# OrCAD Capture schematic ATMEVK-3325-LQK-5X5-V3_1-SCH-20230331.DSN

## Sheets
1 10. VCCIO Source: size B; title: ATM3325 EVALUATION BOARD; rev: 3.1; note: 082-30-610-xxxx
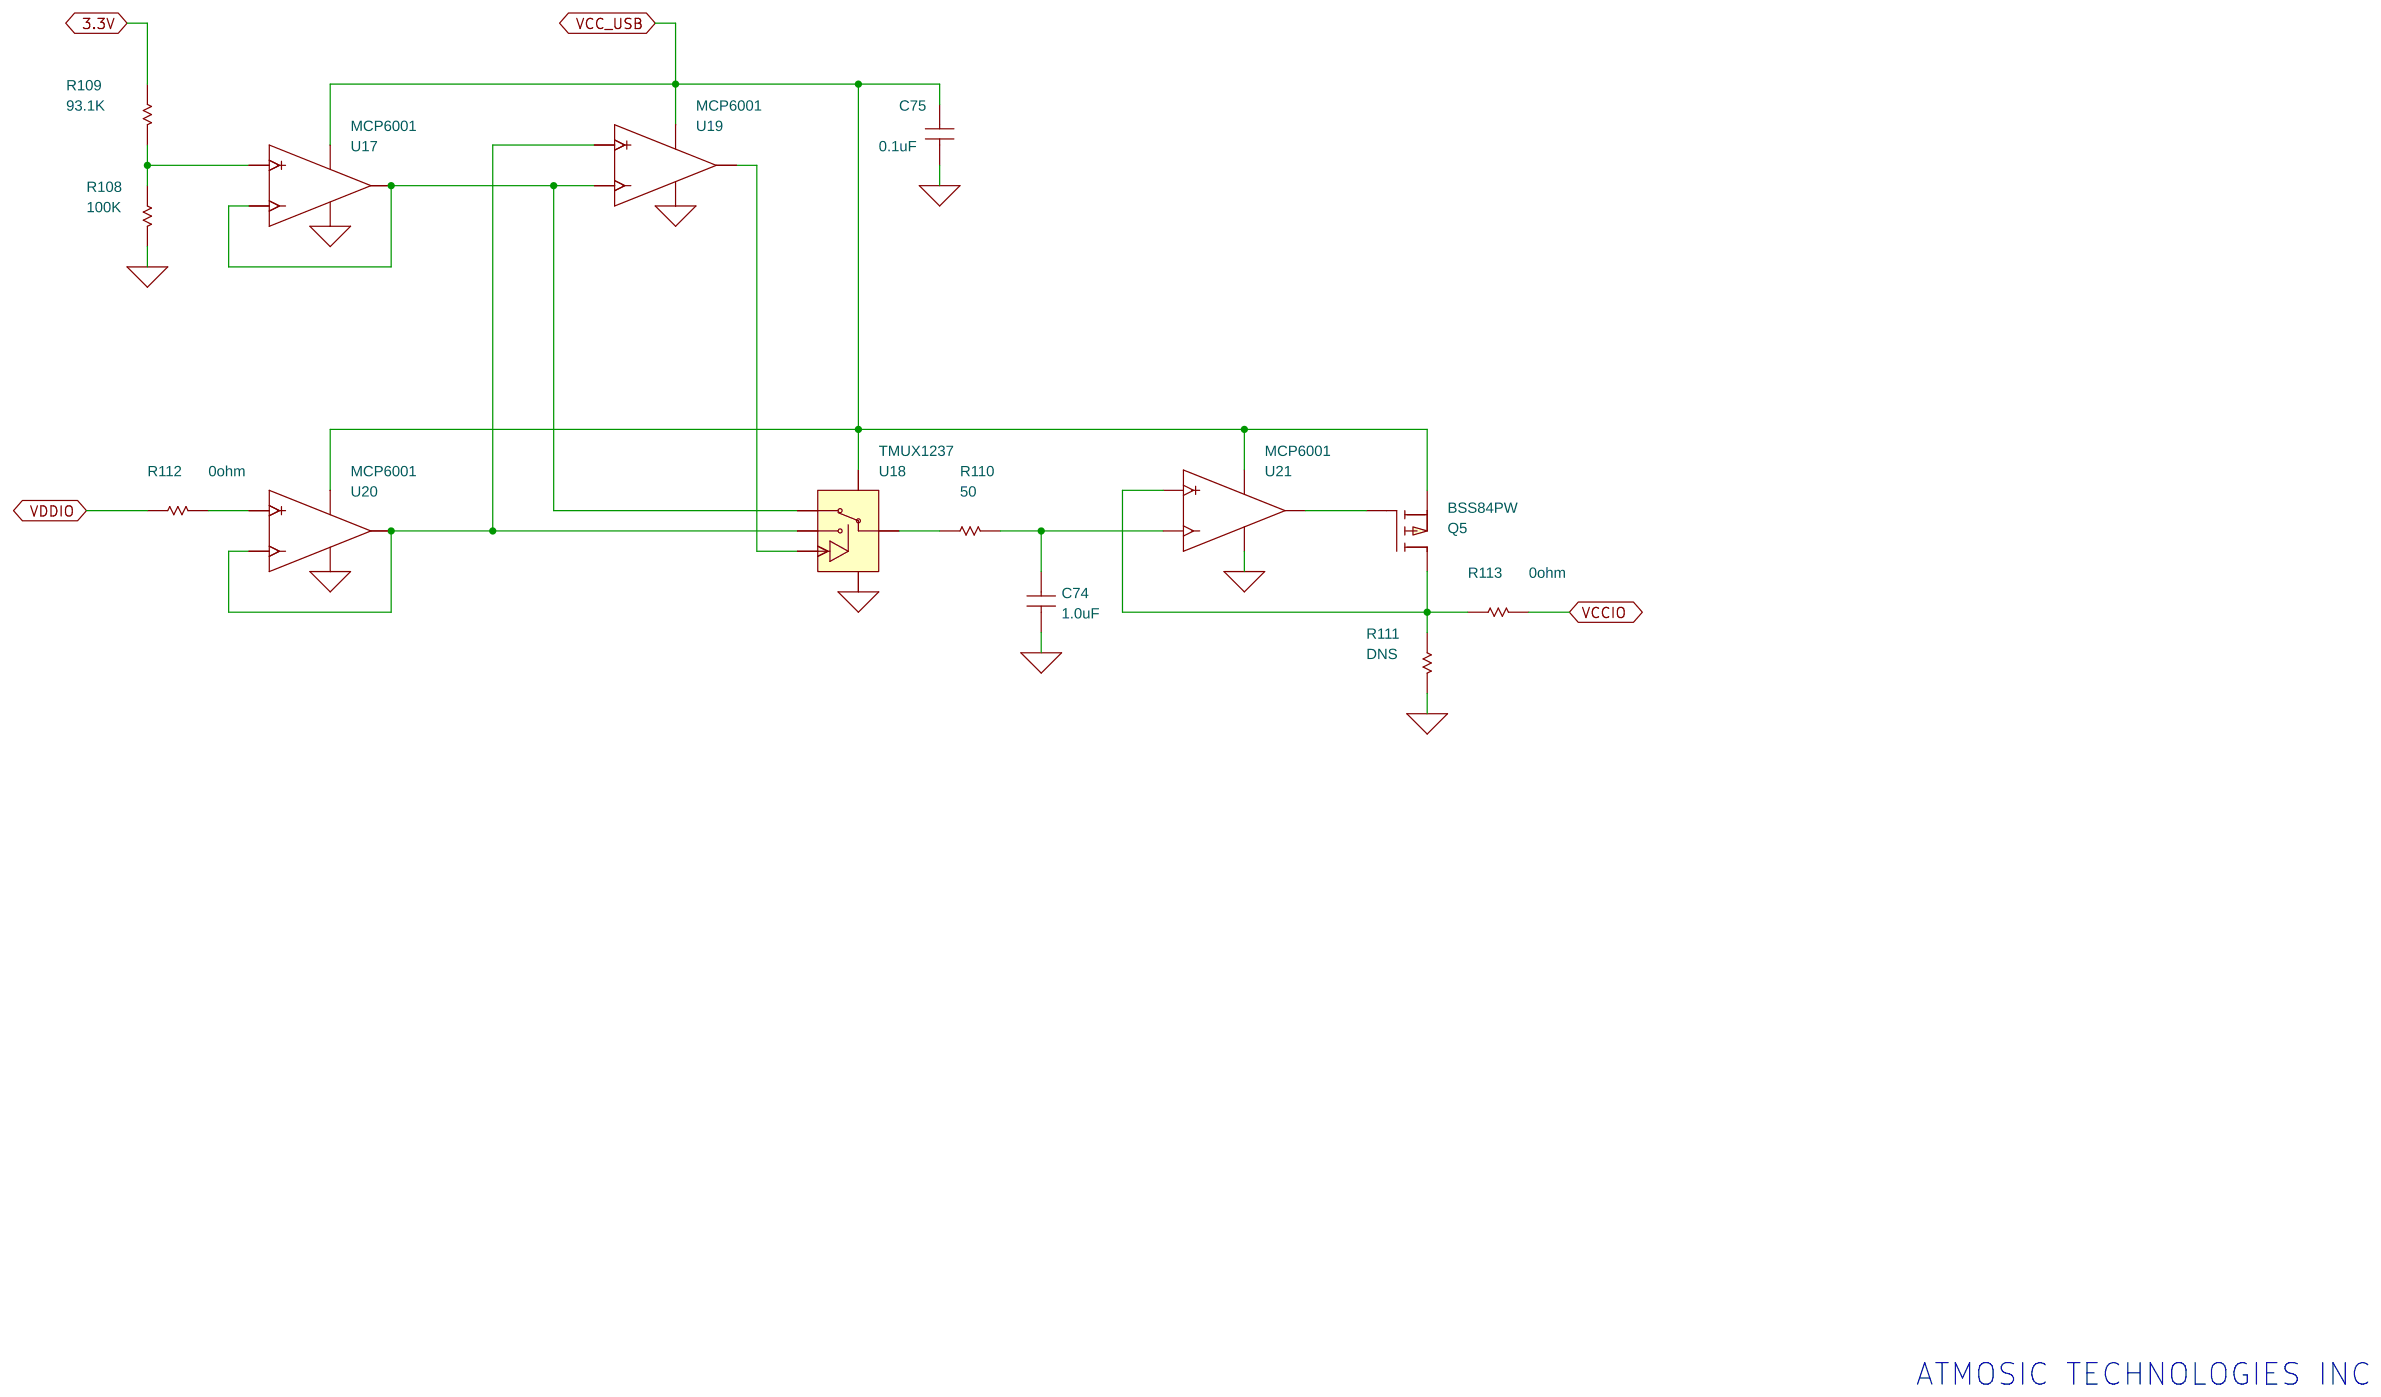
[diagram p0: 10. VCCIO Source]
2 01. TITLE: title: ATM3325 w/ EXTENDED STORAGE EVALUATION BOARD
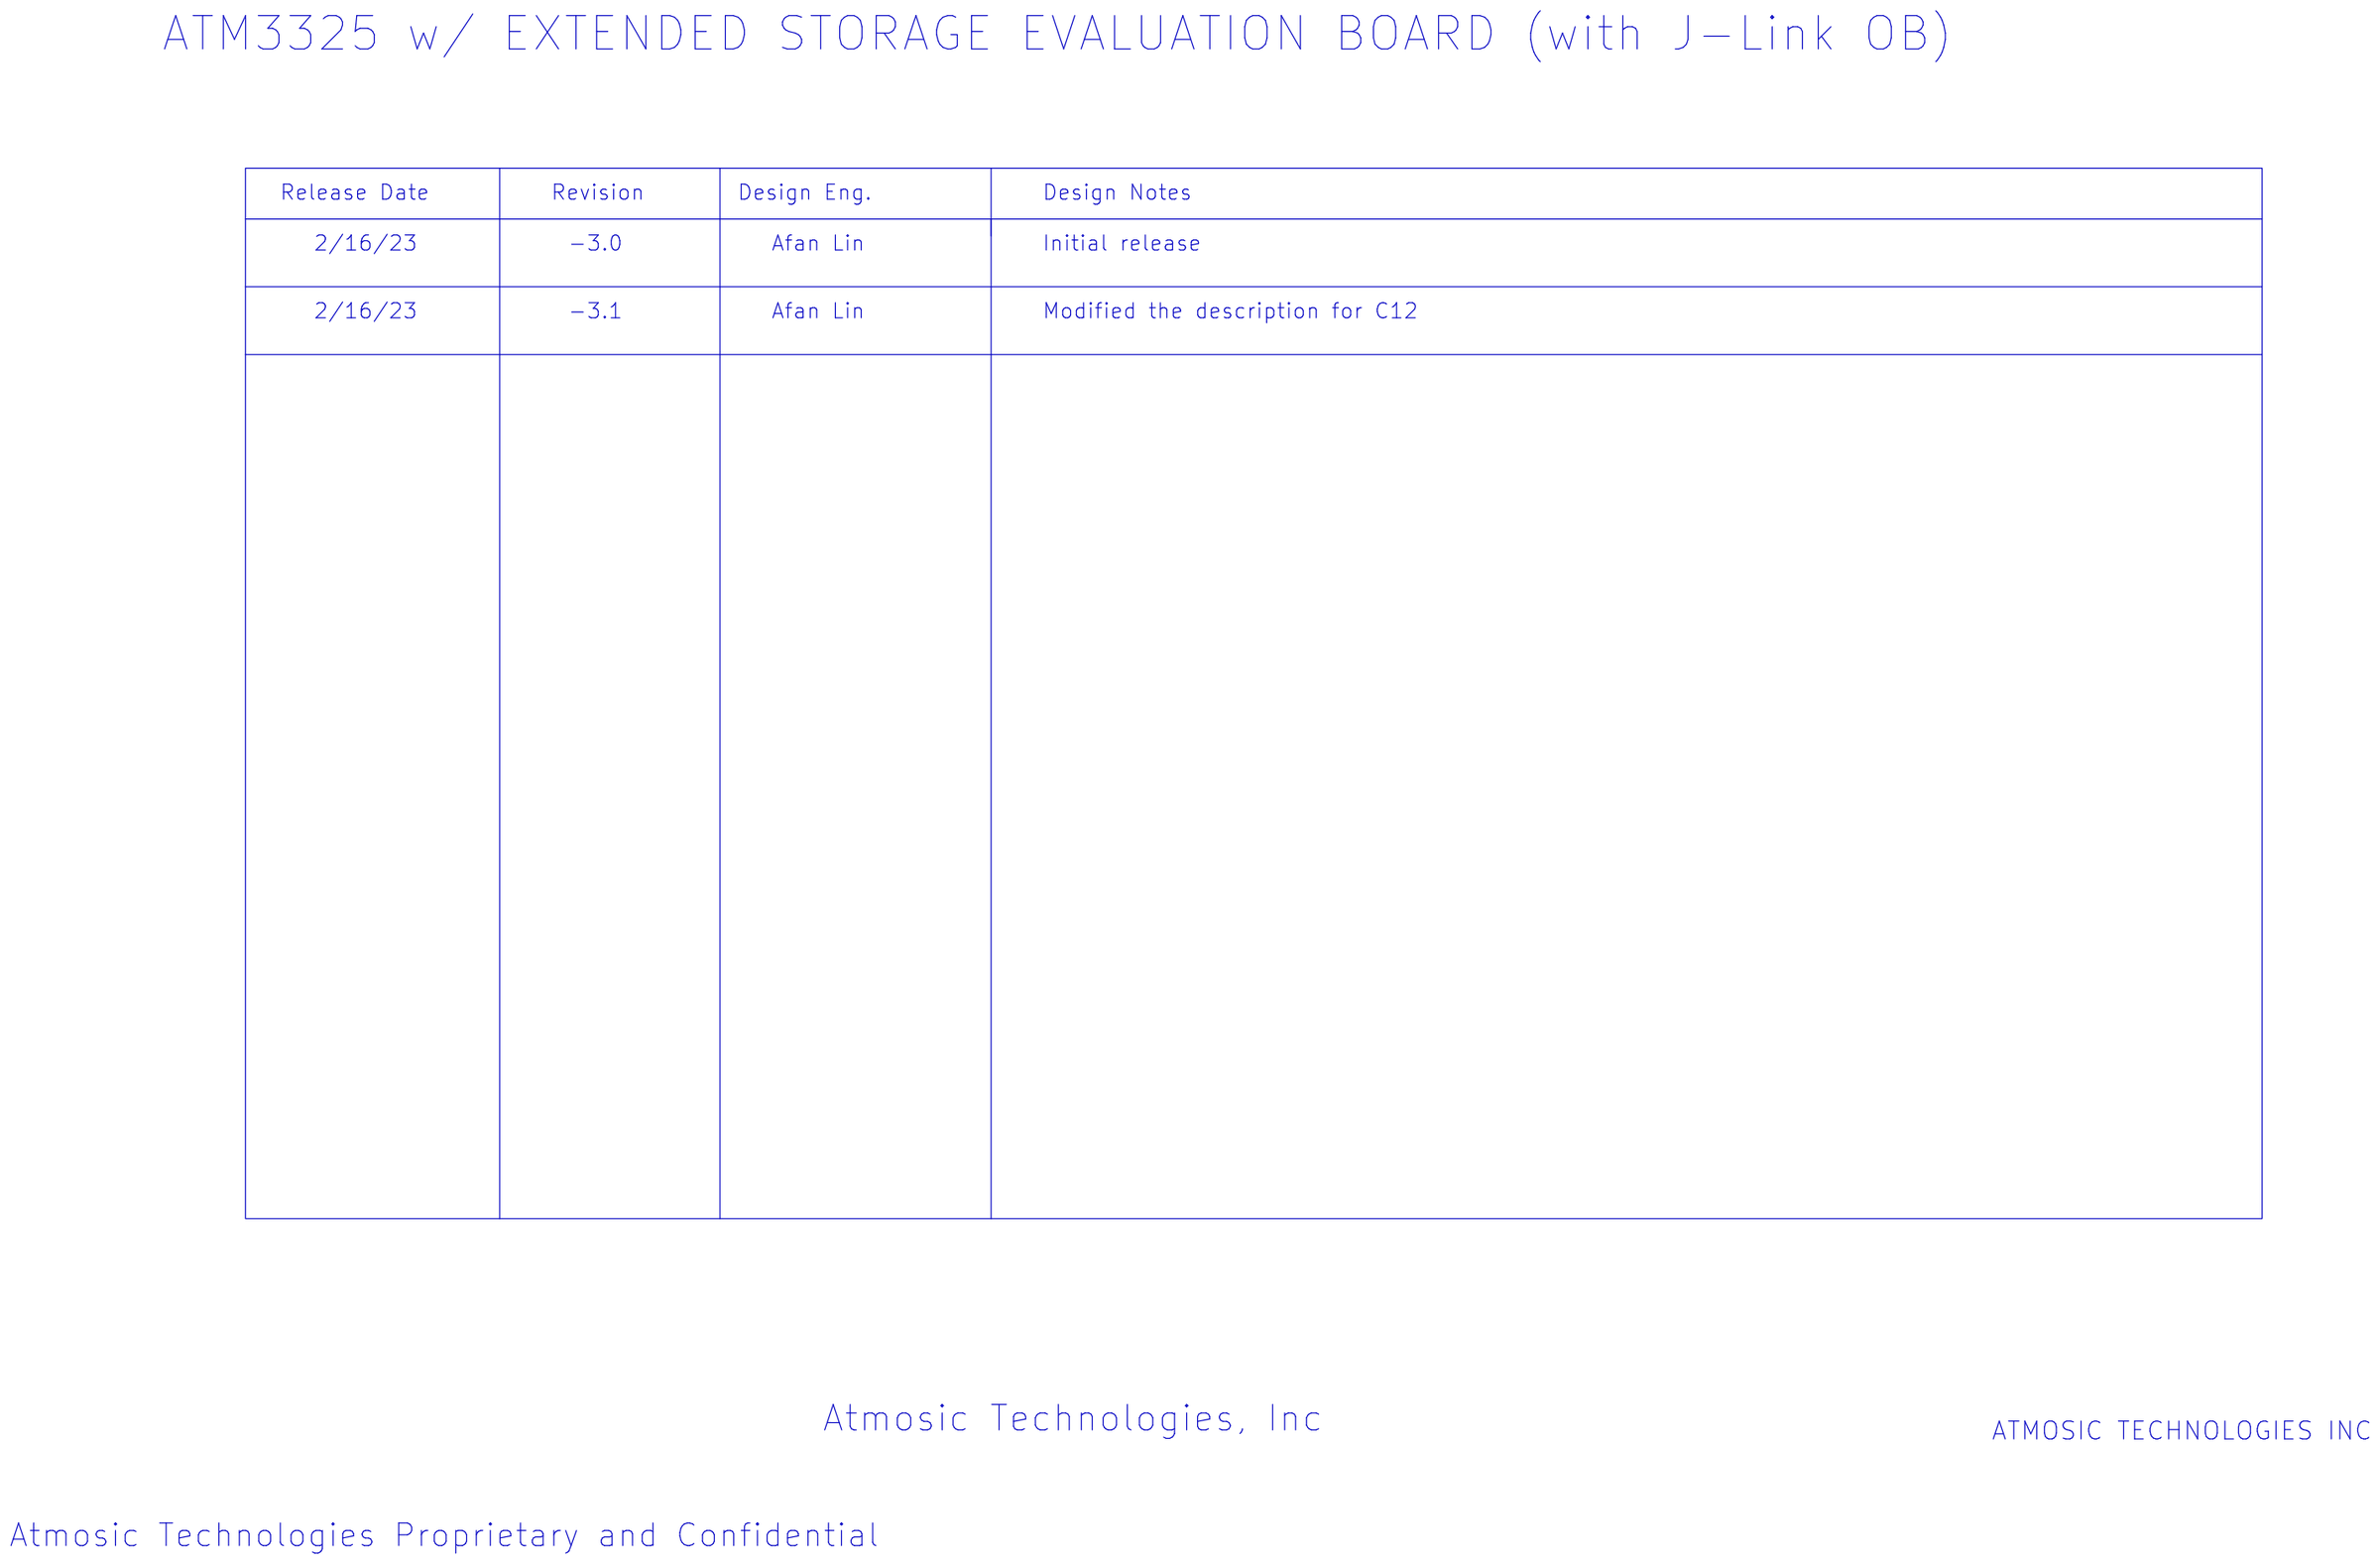
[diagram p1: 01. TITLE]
3 02. Block Diagram
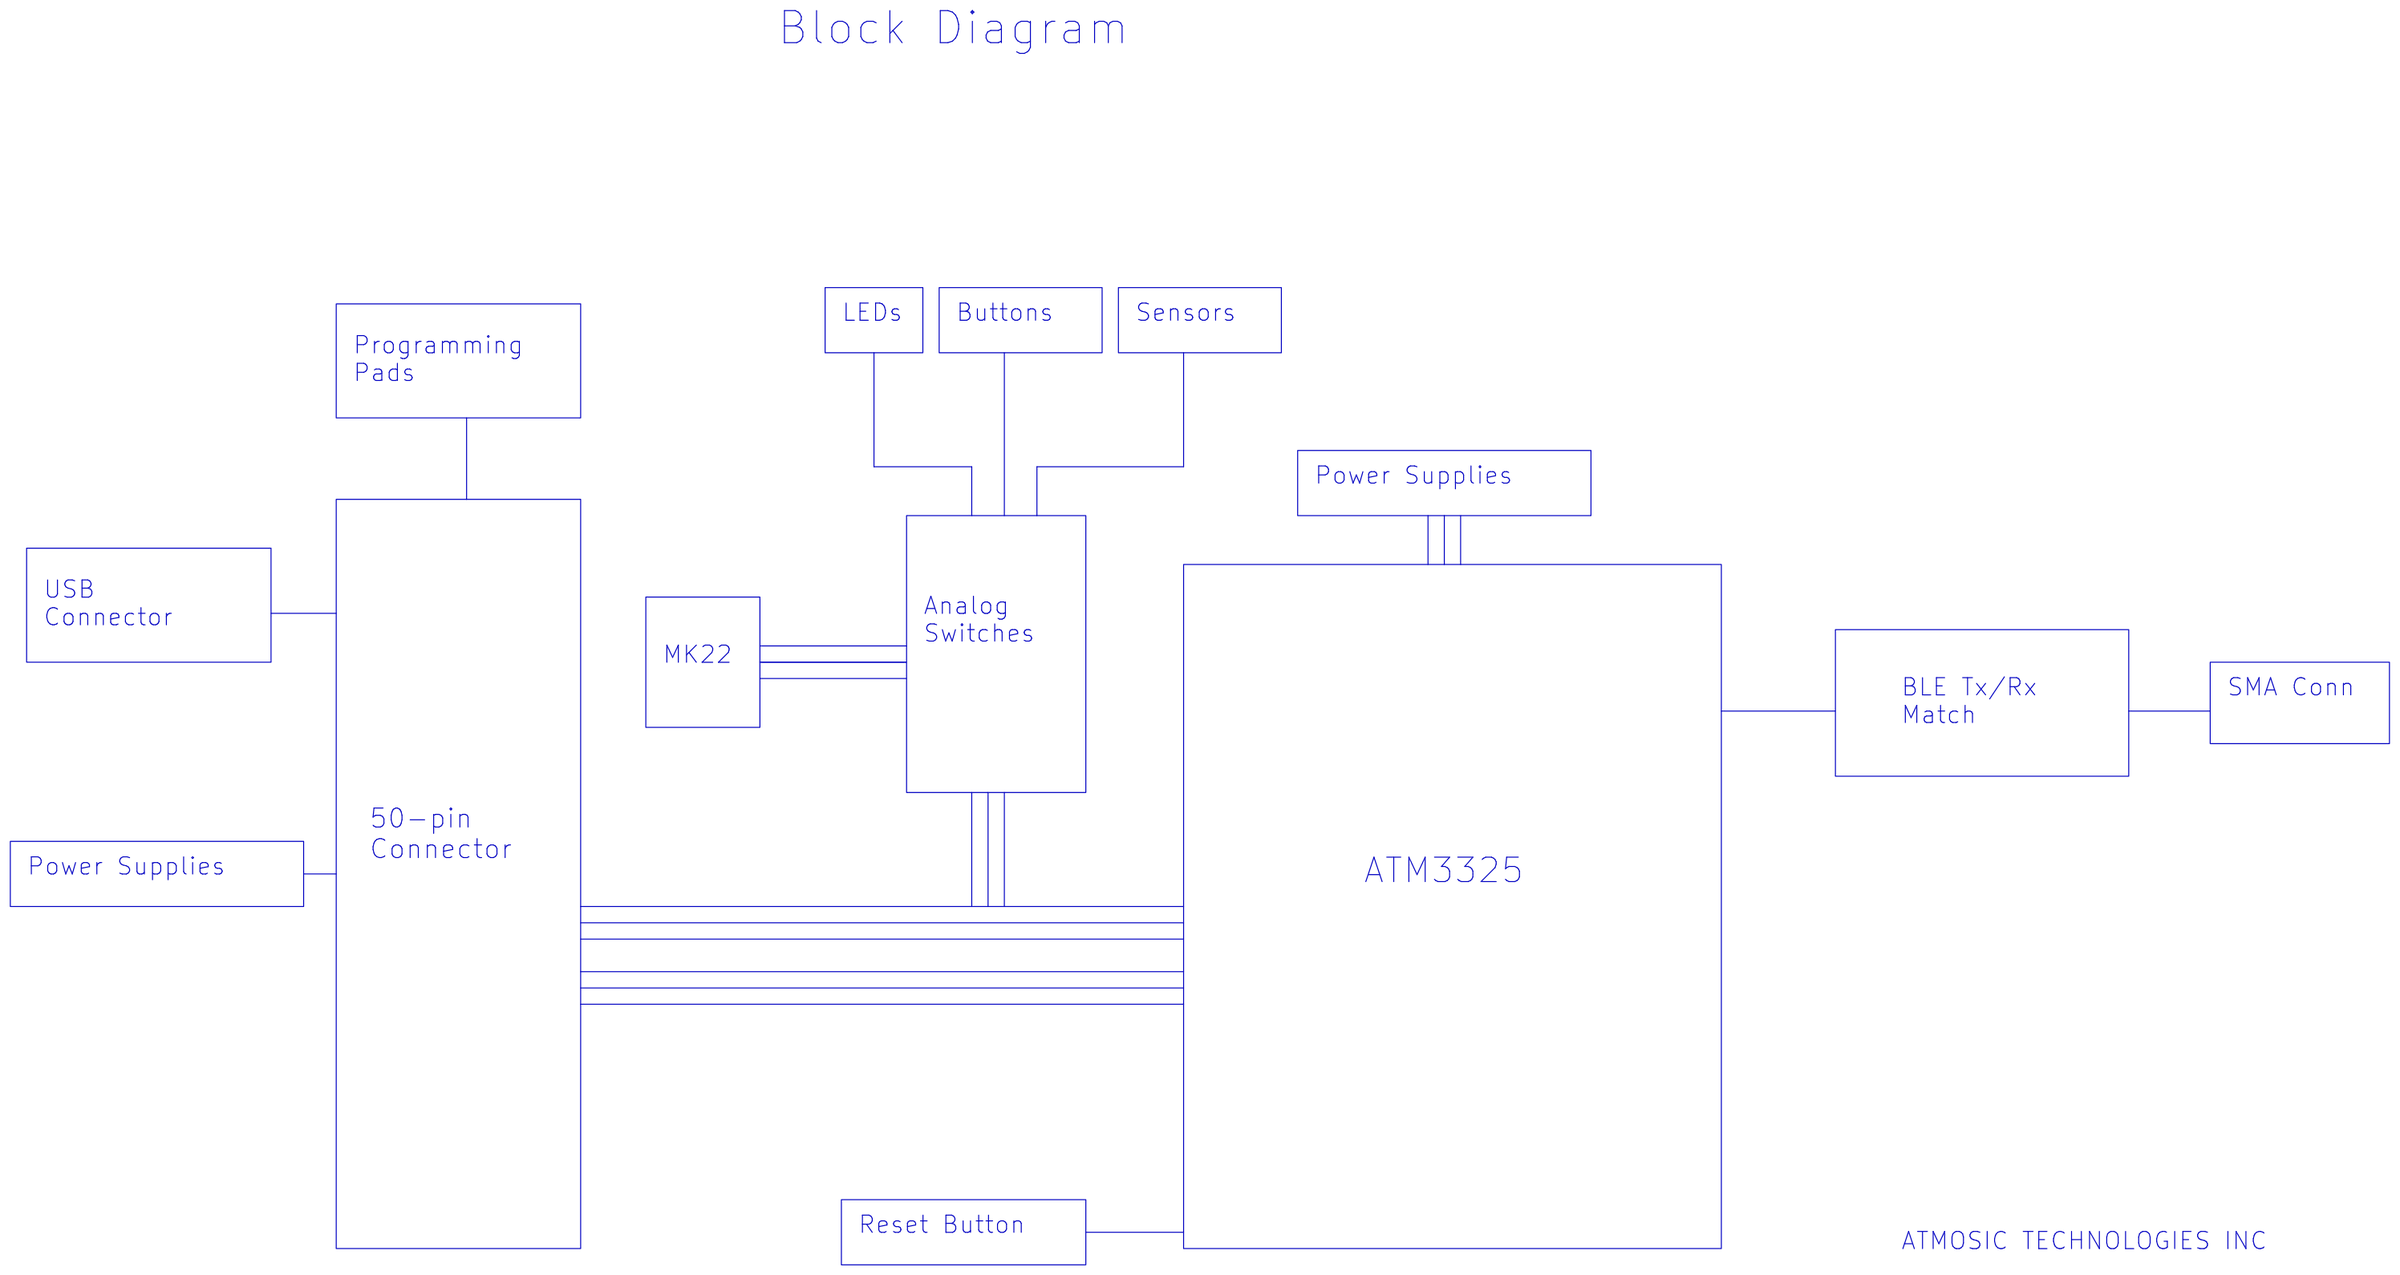
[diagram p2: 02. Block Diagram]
4 03. ATM3325: size B; title: ATM3330e EVALUATION BOARD
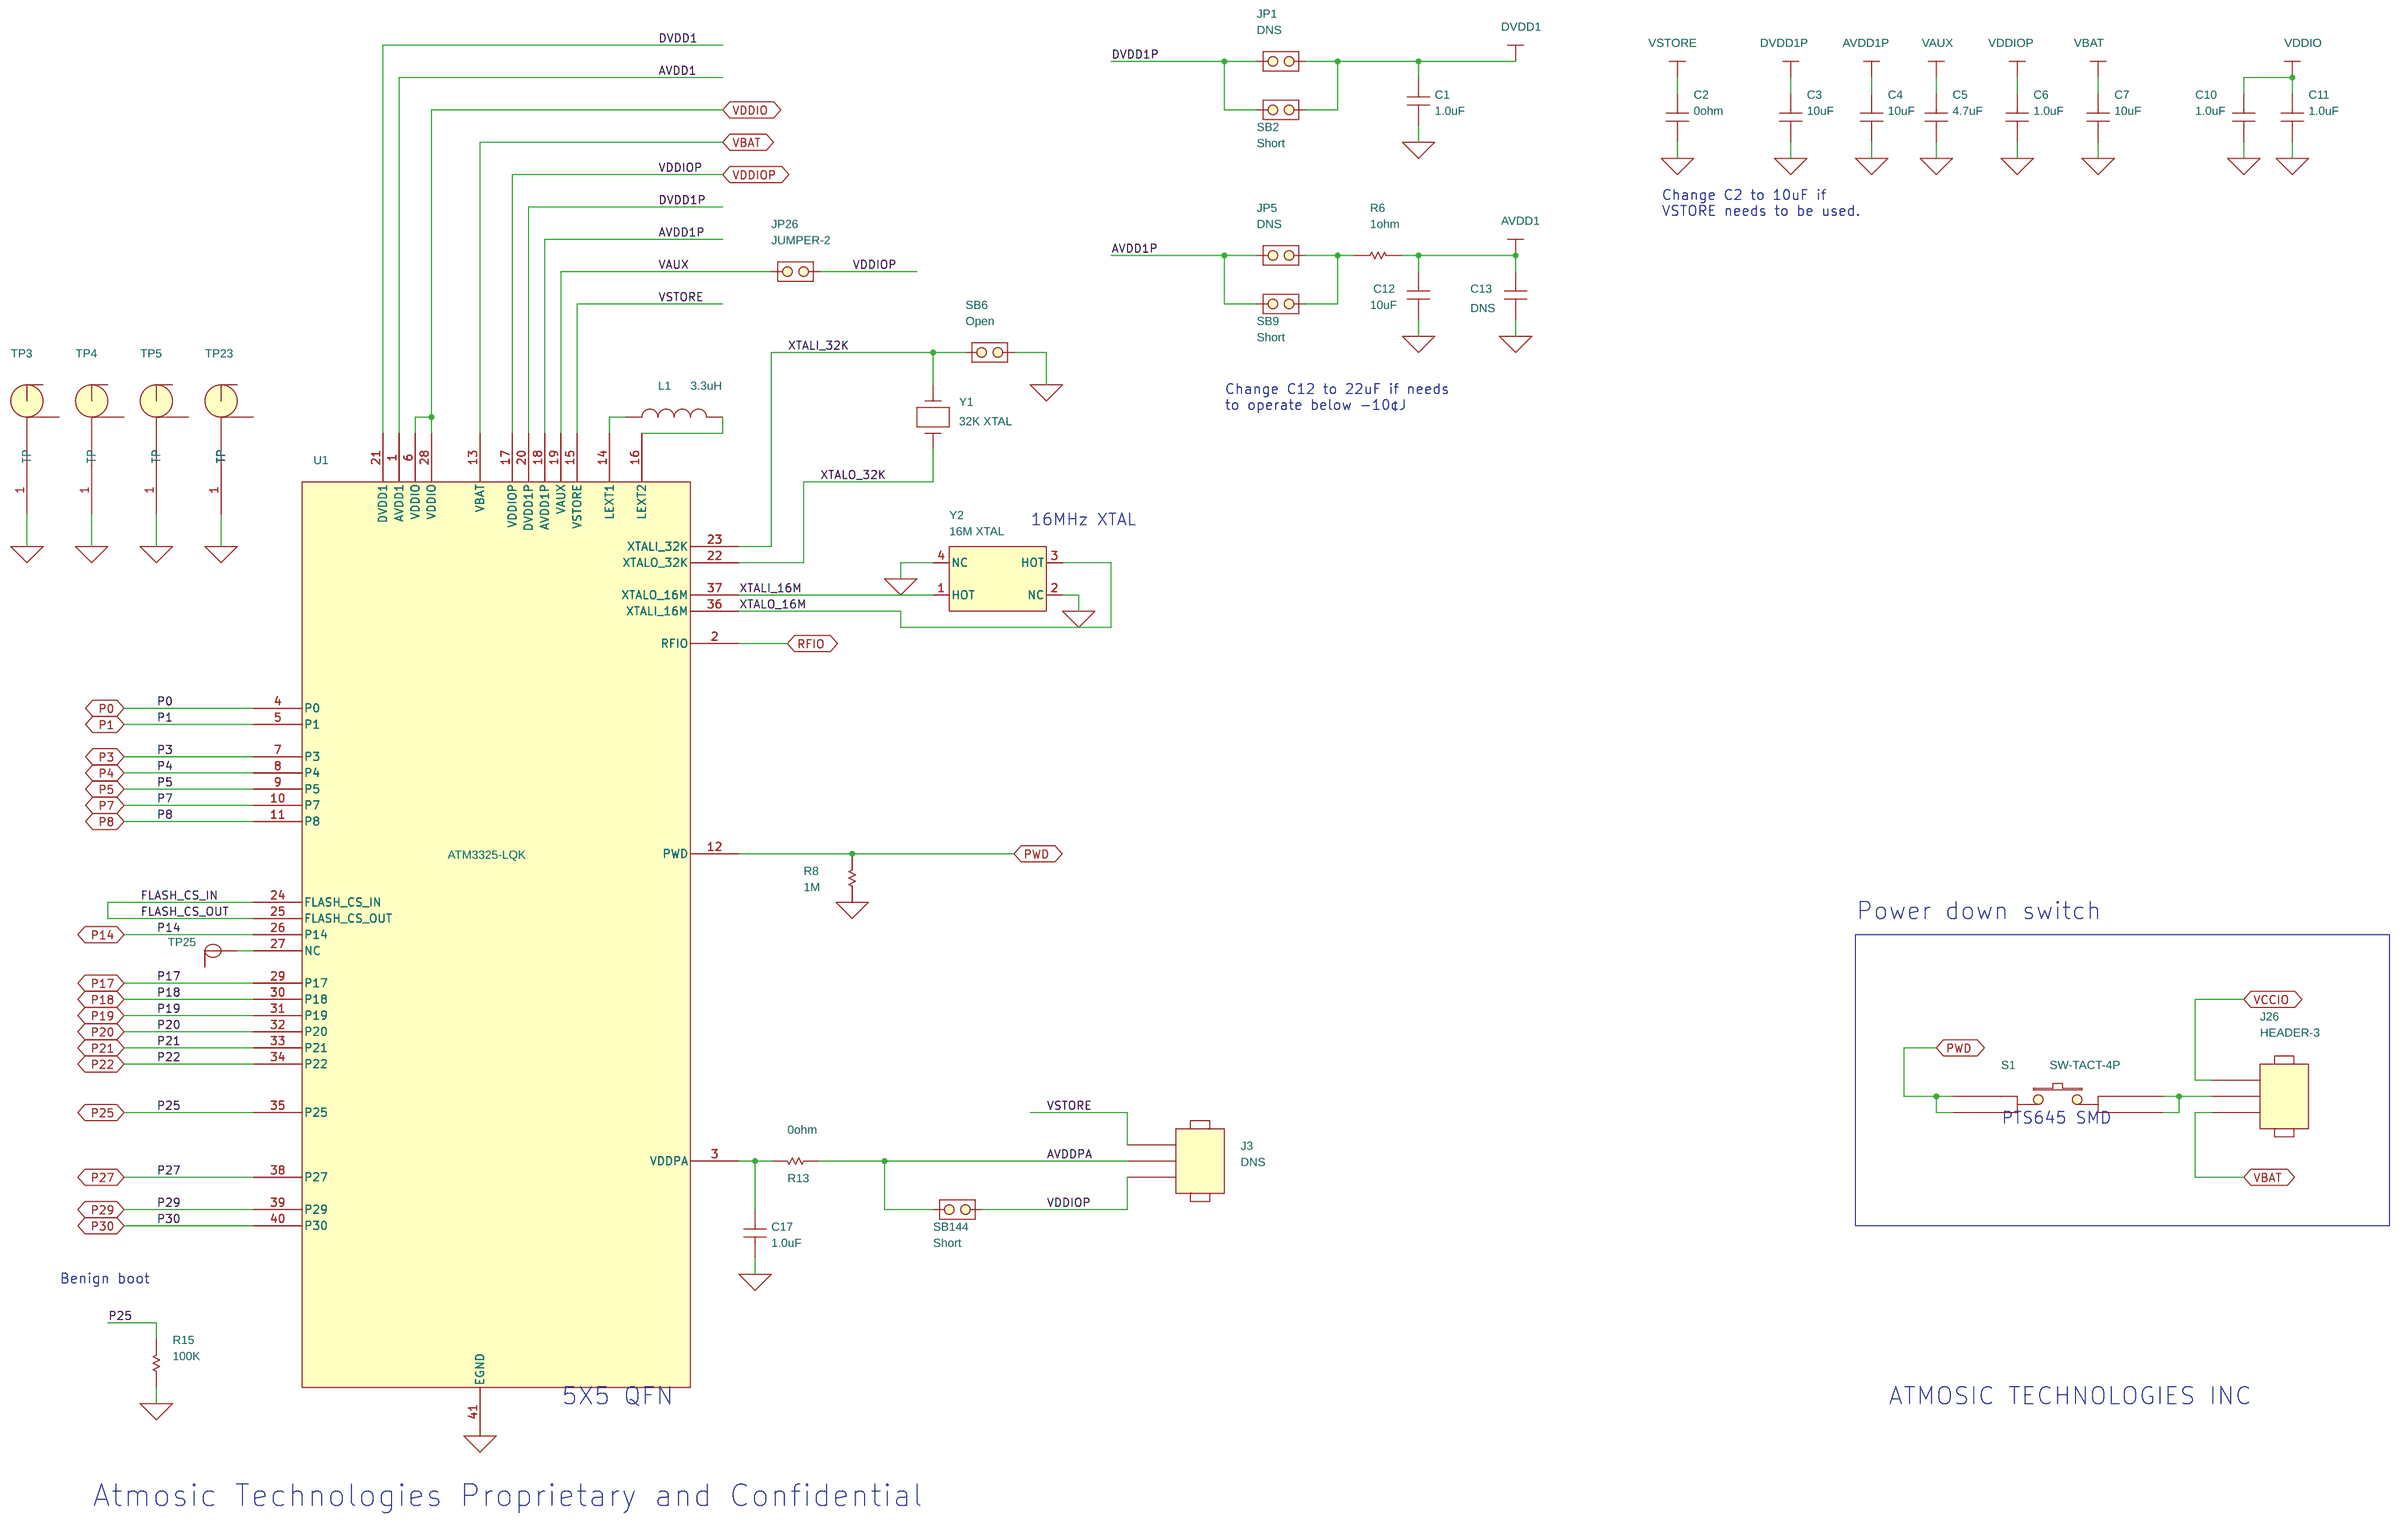
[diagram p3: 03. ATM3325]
5 04. GPIO Mapping: size B
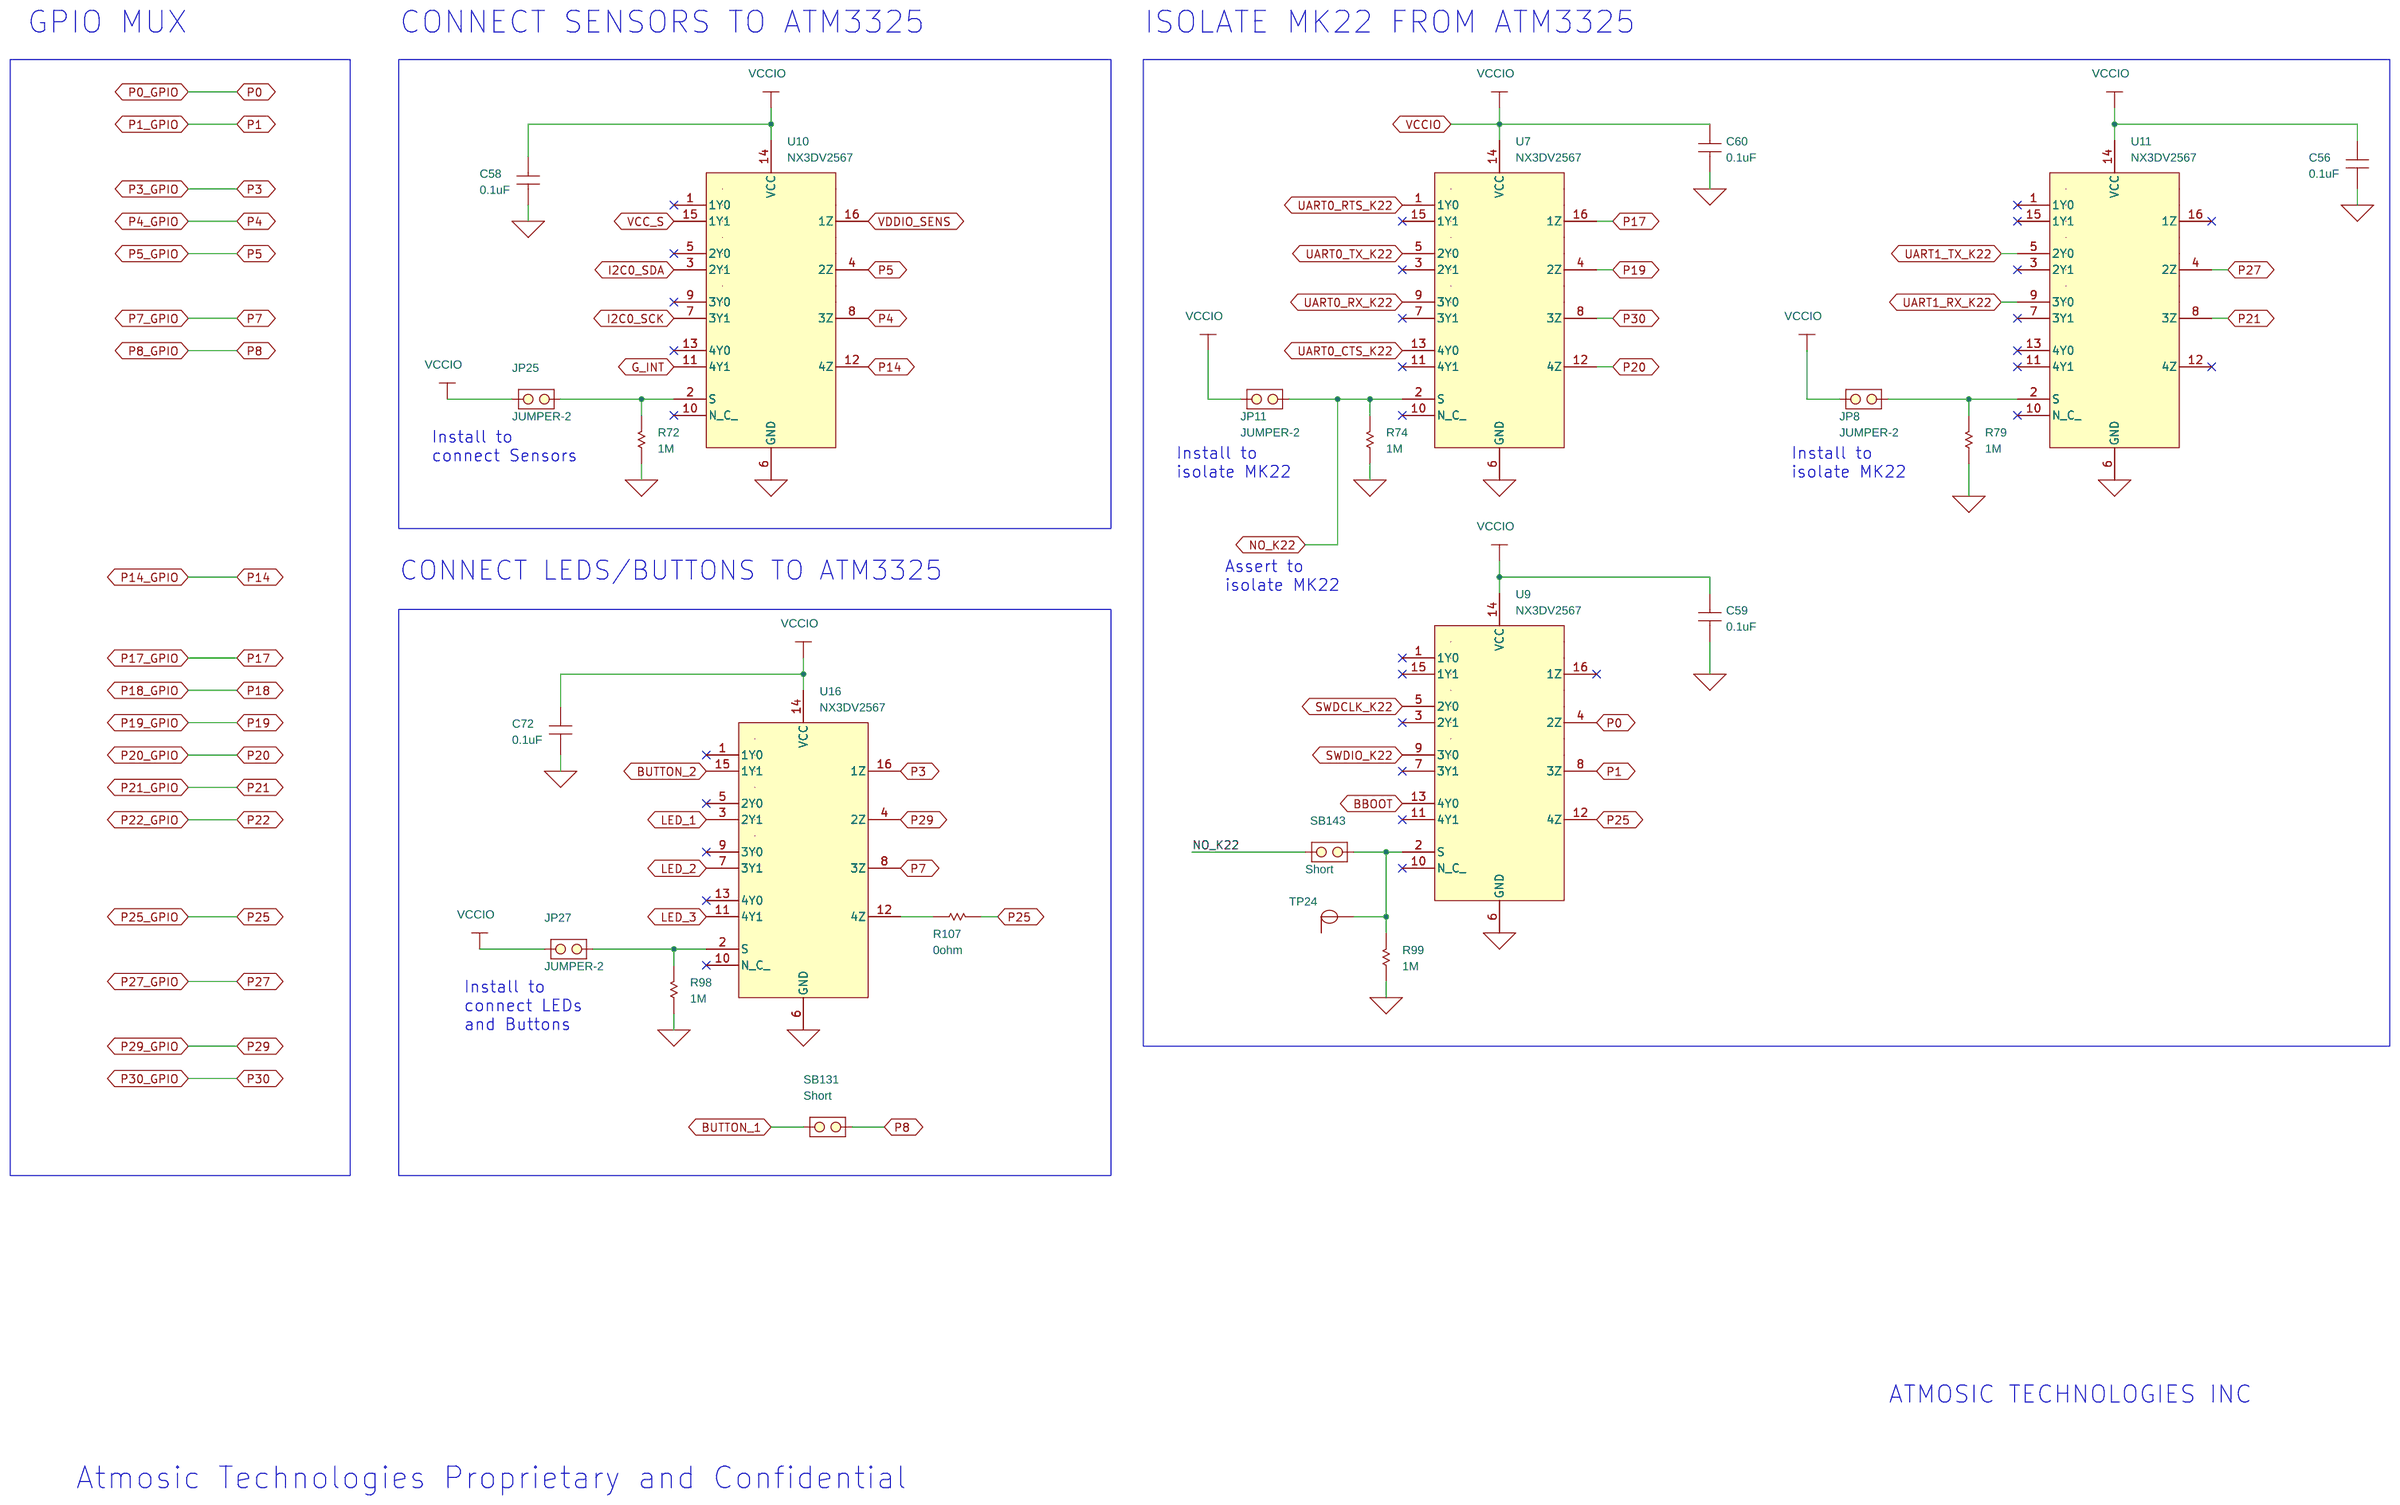
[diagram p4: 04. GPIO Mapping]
6 05. RF (RFIO): size B
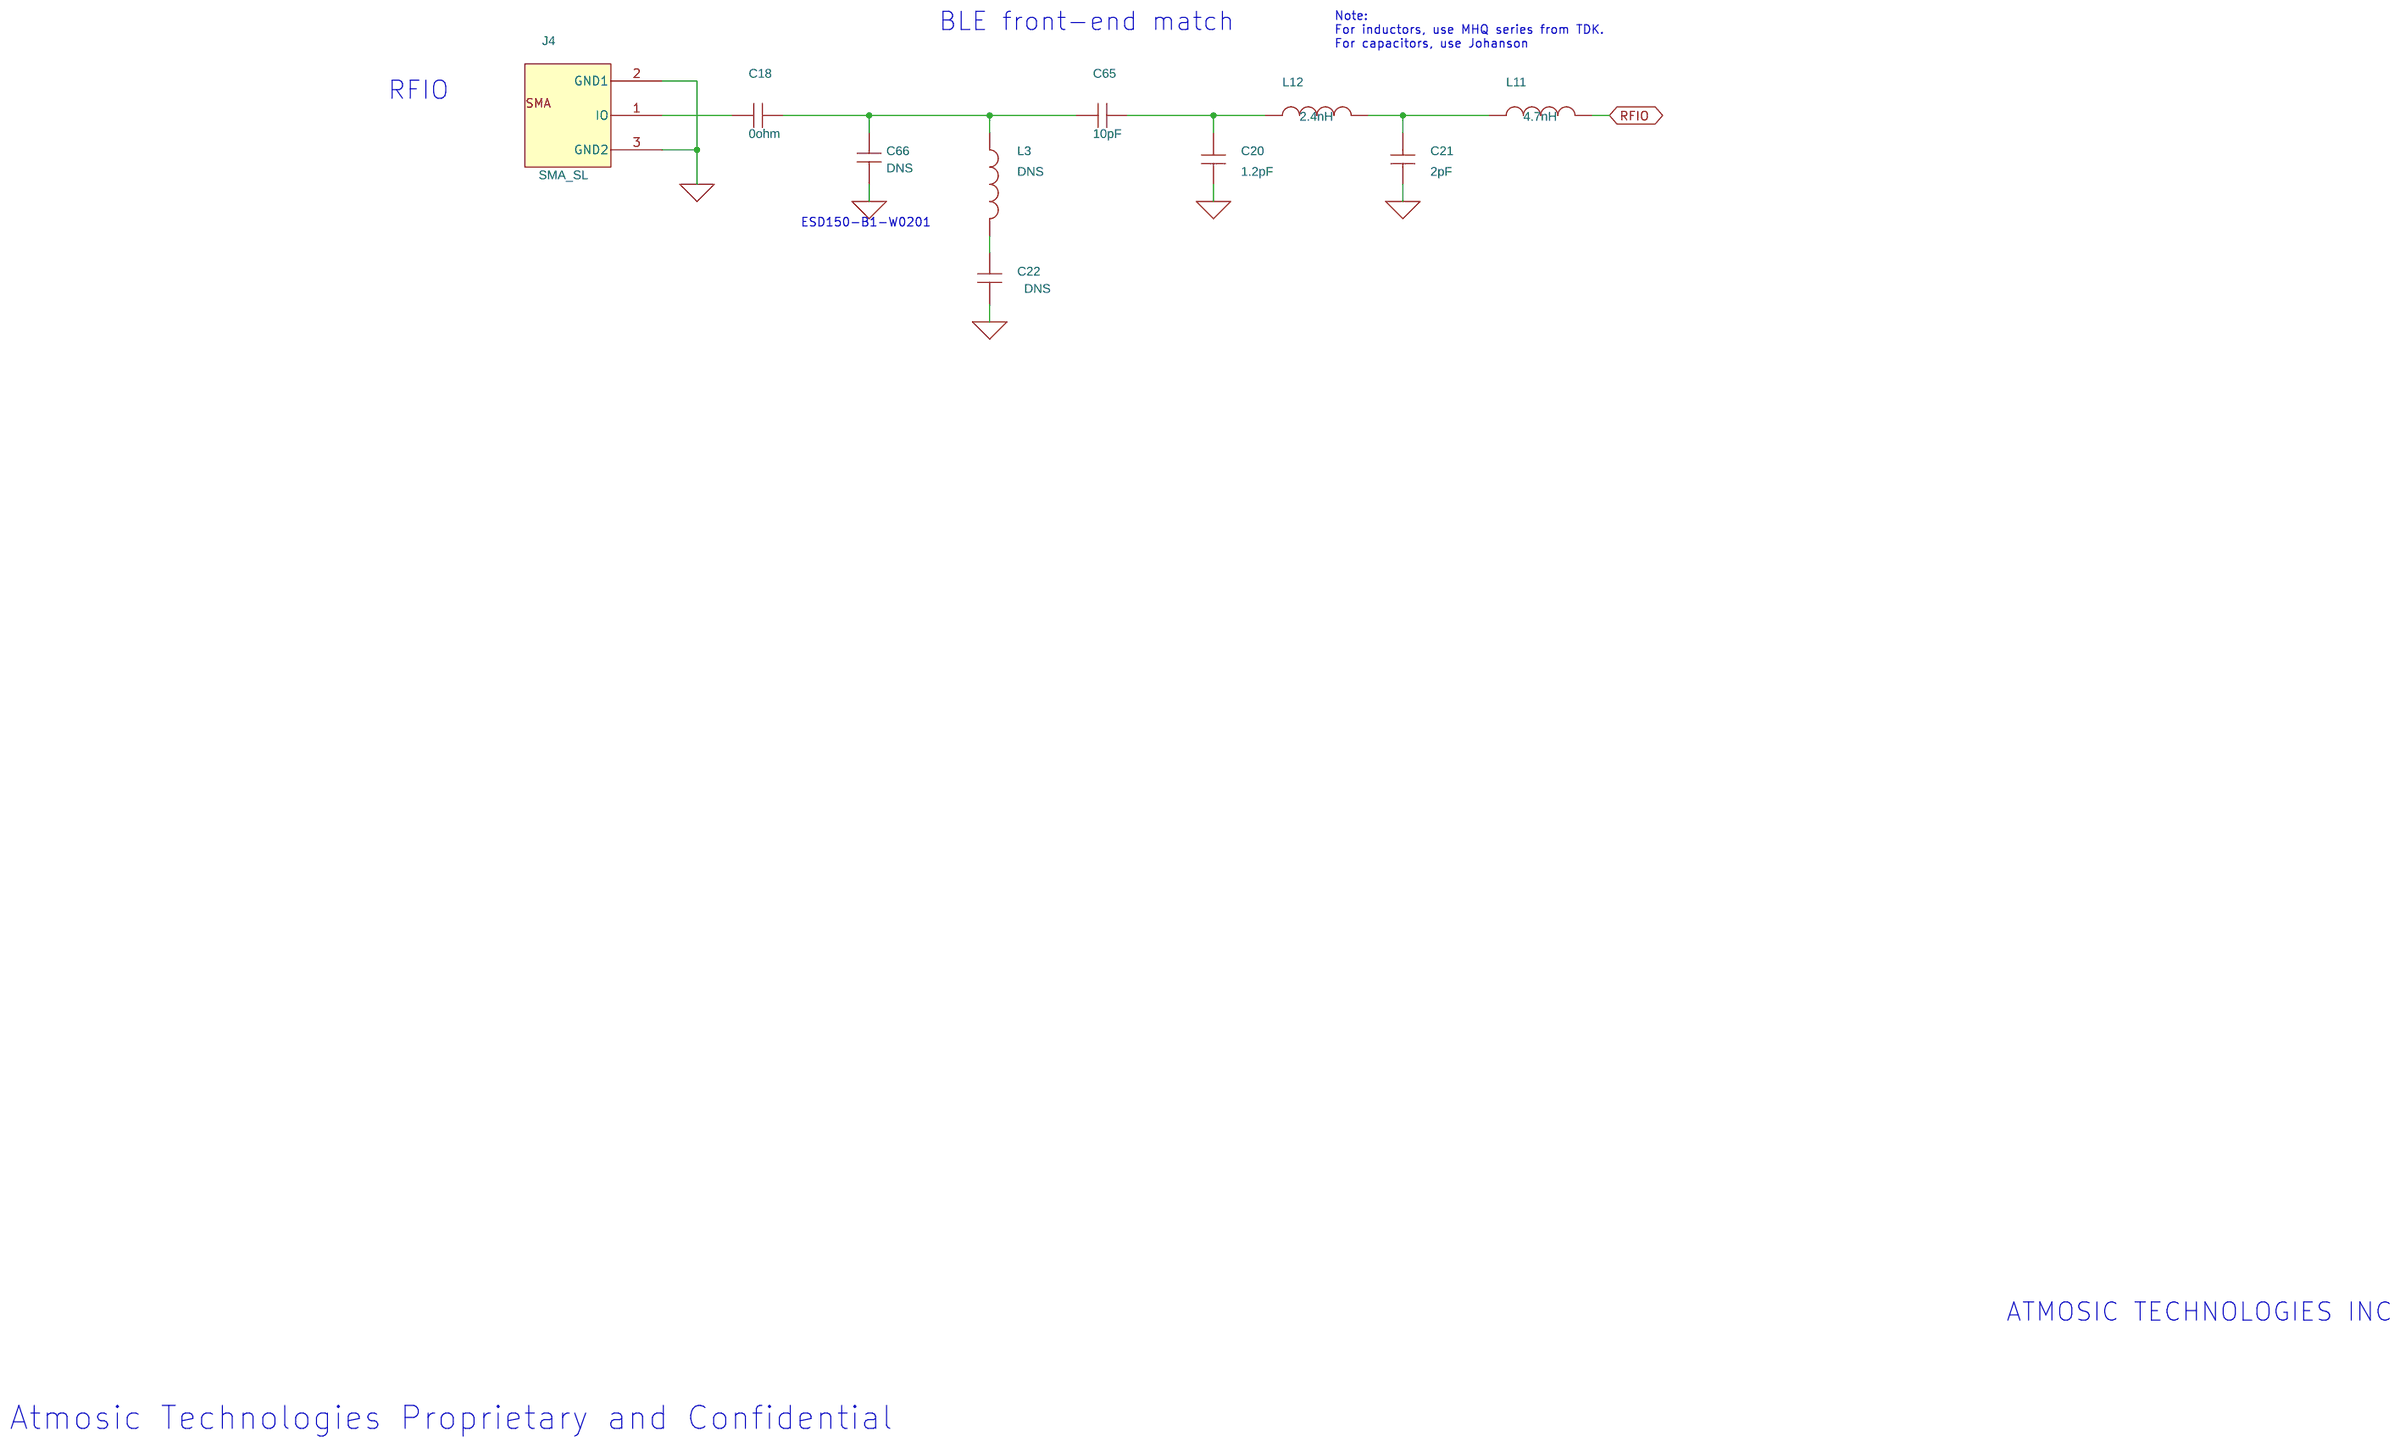
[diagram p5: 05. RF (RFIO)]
7 06. Buttons LEDs Sensors: size B
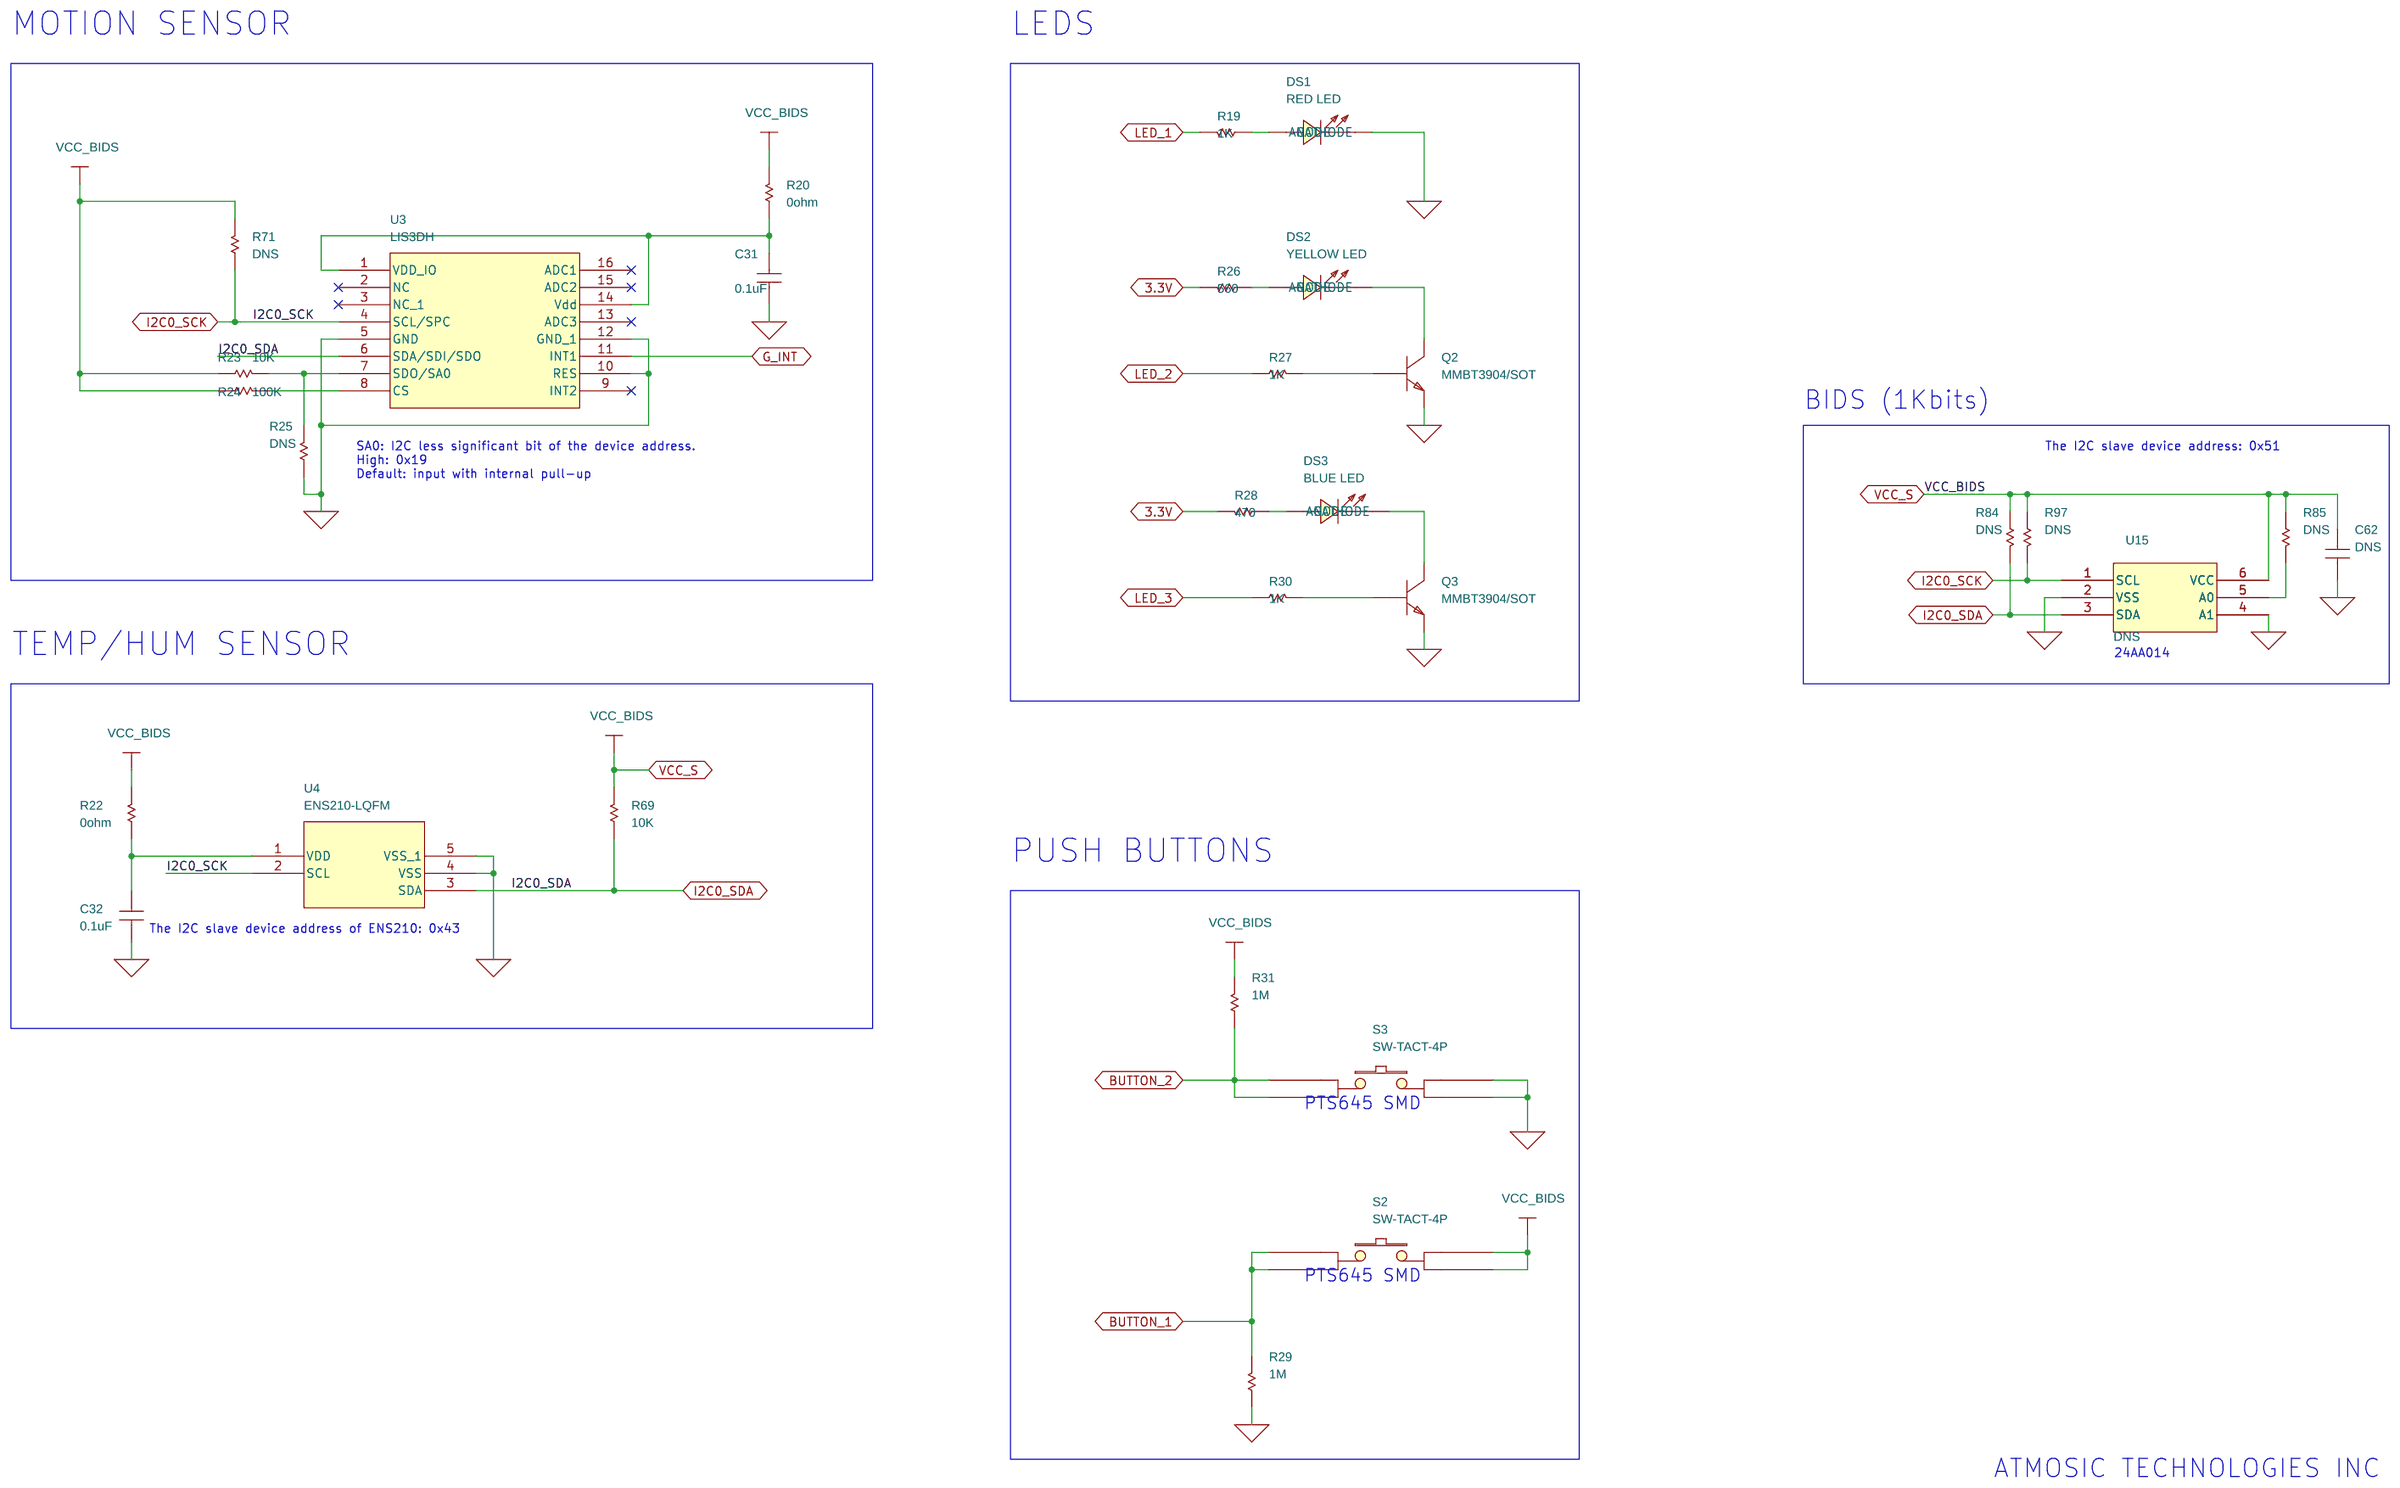
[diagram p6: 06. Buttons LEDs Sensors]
8 07. Connectors: size B
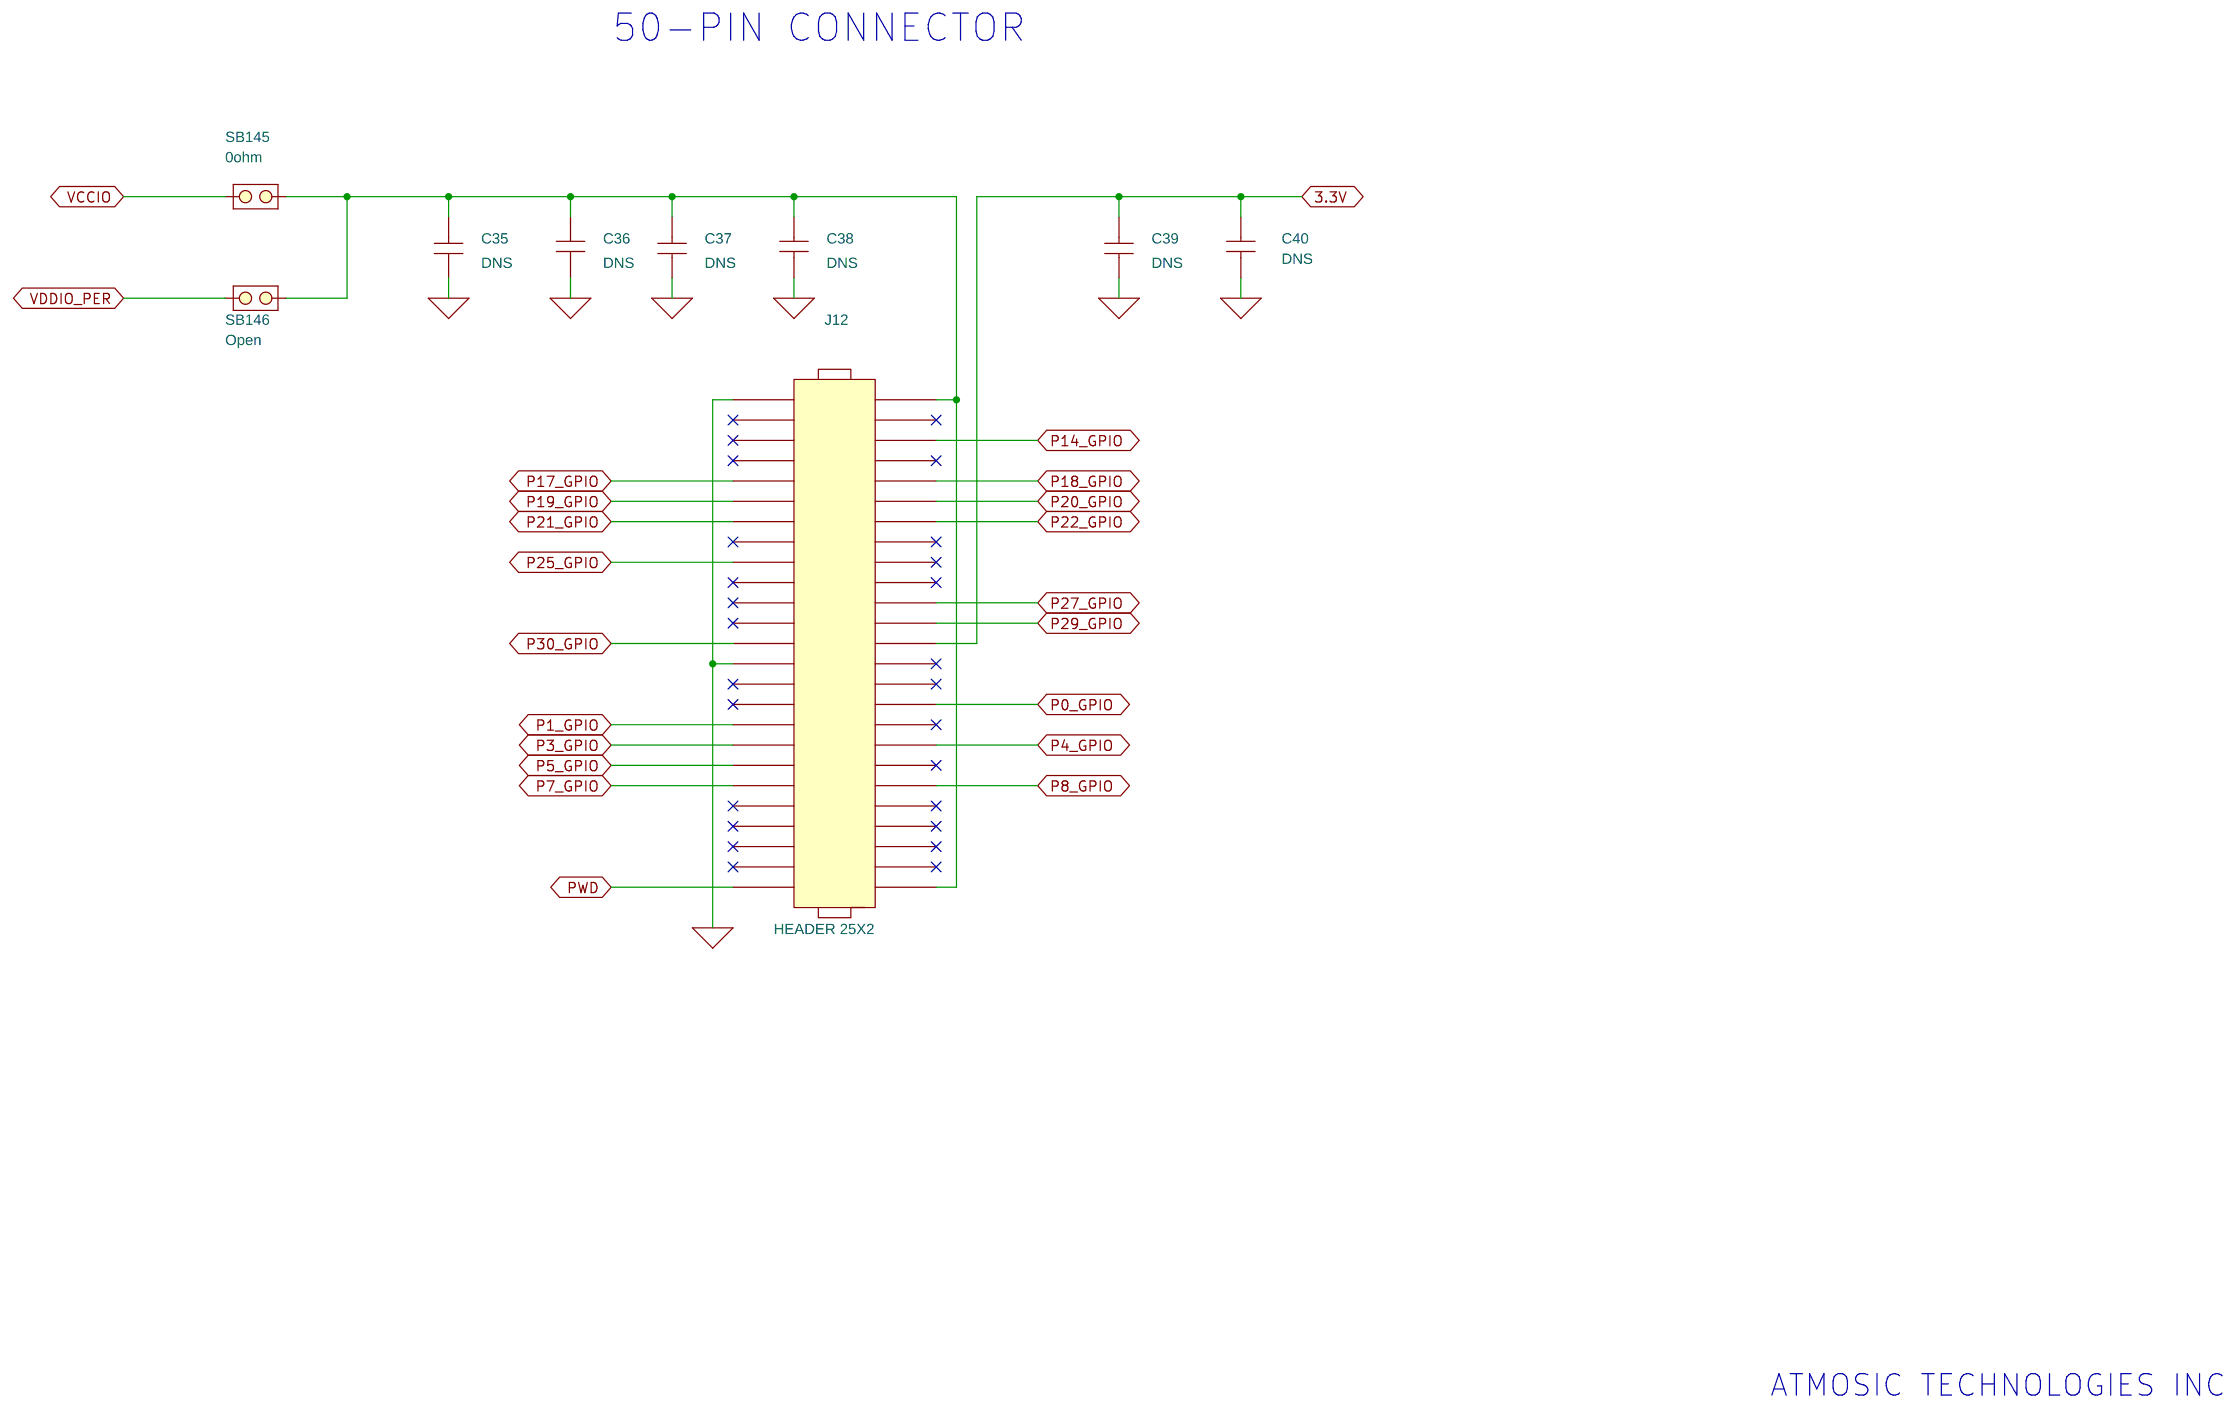
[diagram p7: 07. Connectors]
9 08. MK22: size B
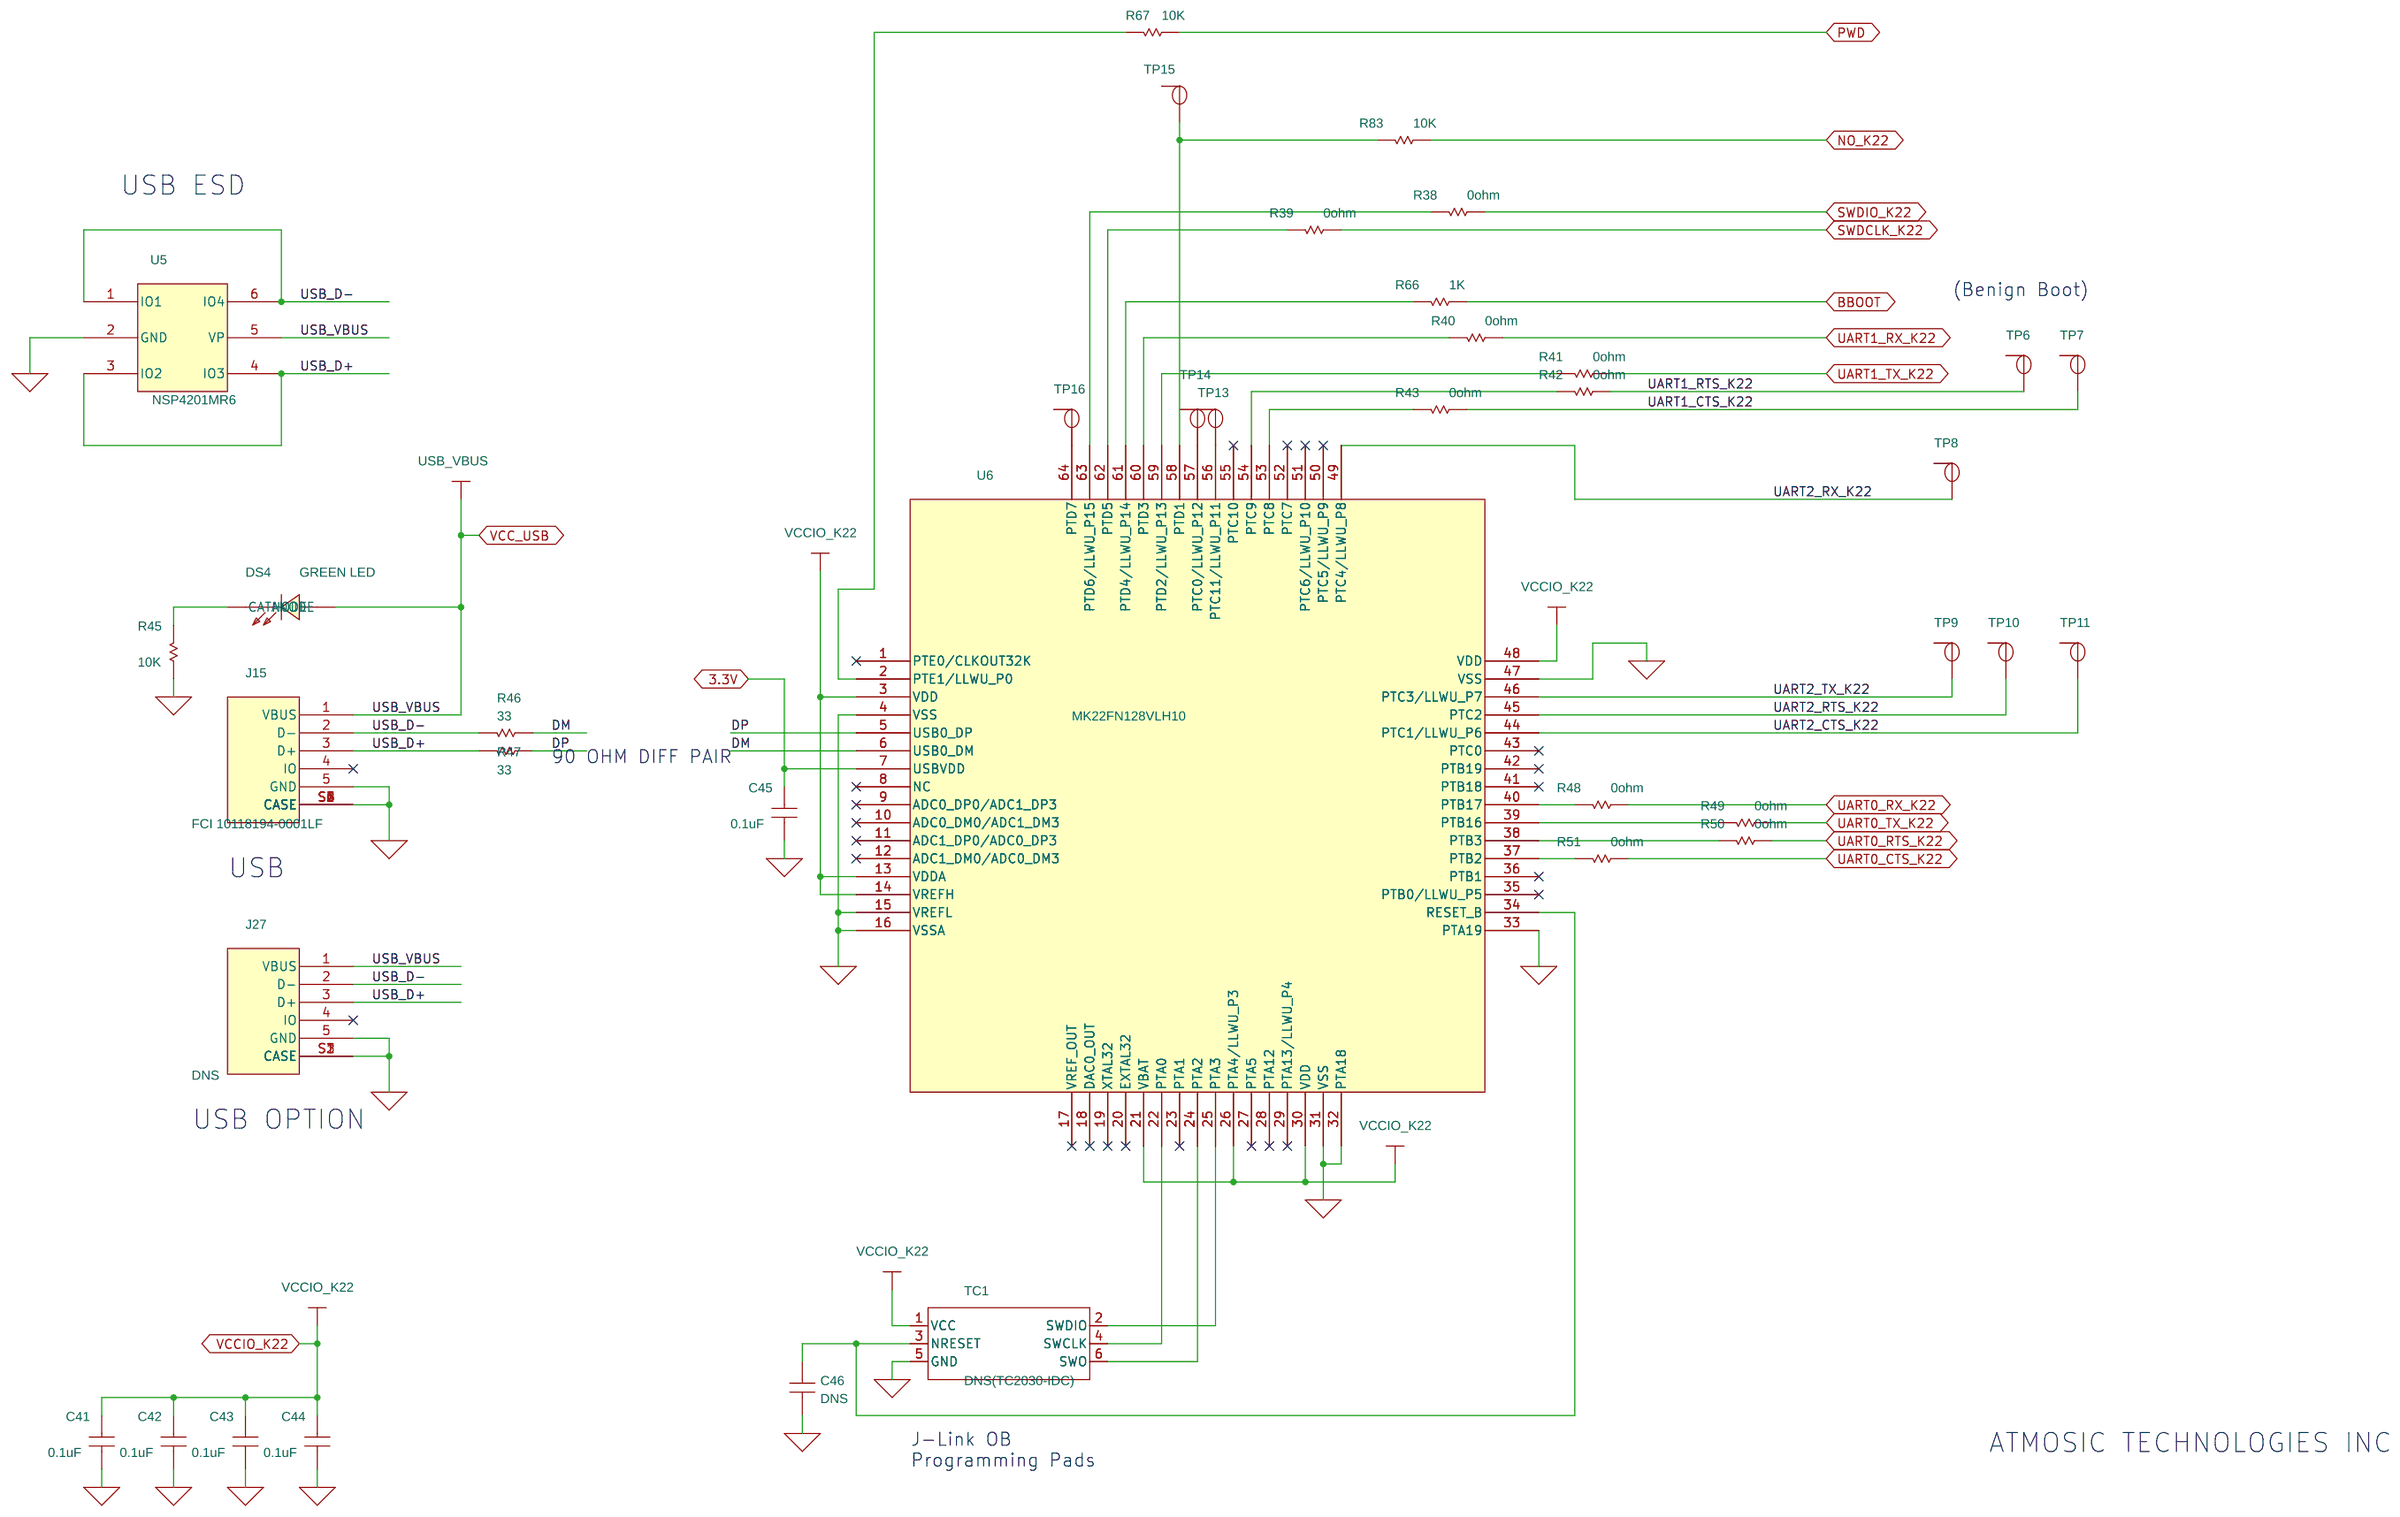
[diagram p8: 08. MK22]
10 09. Power: size B
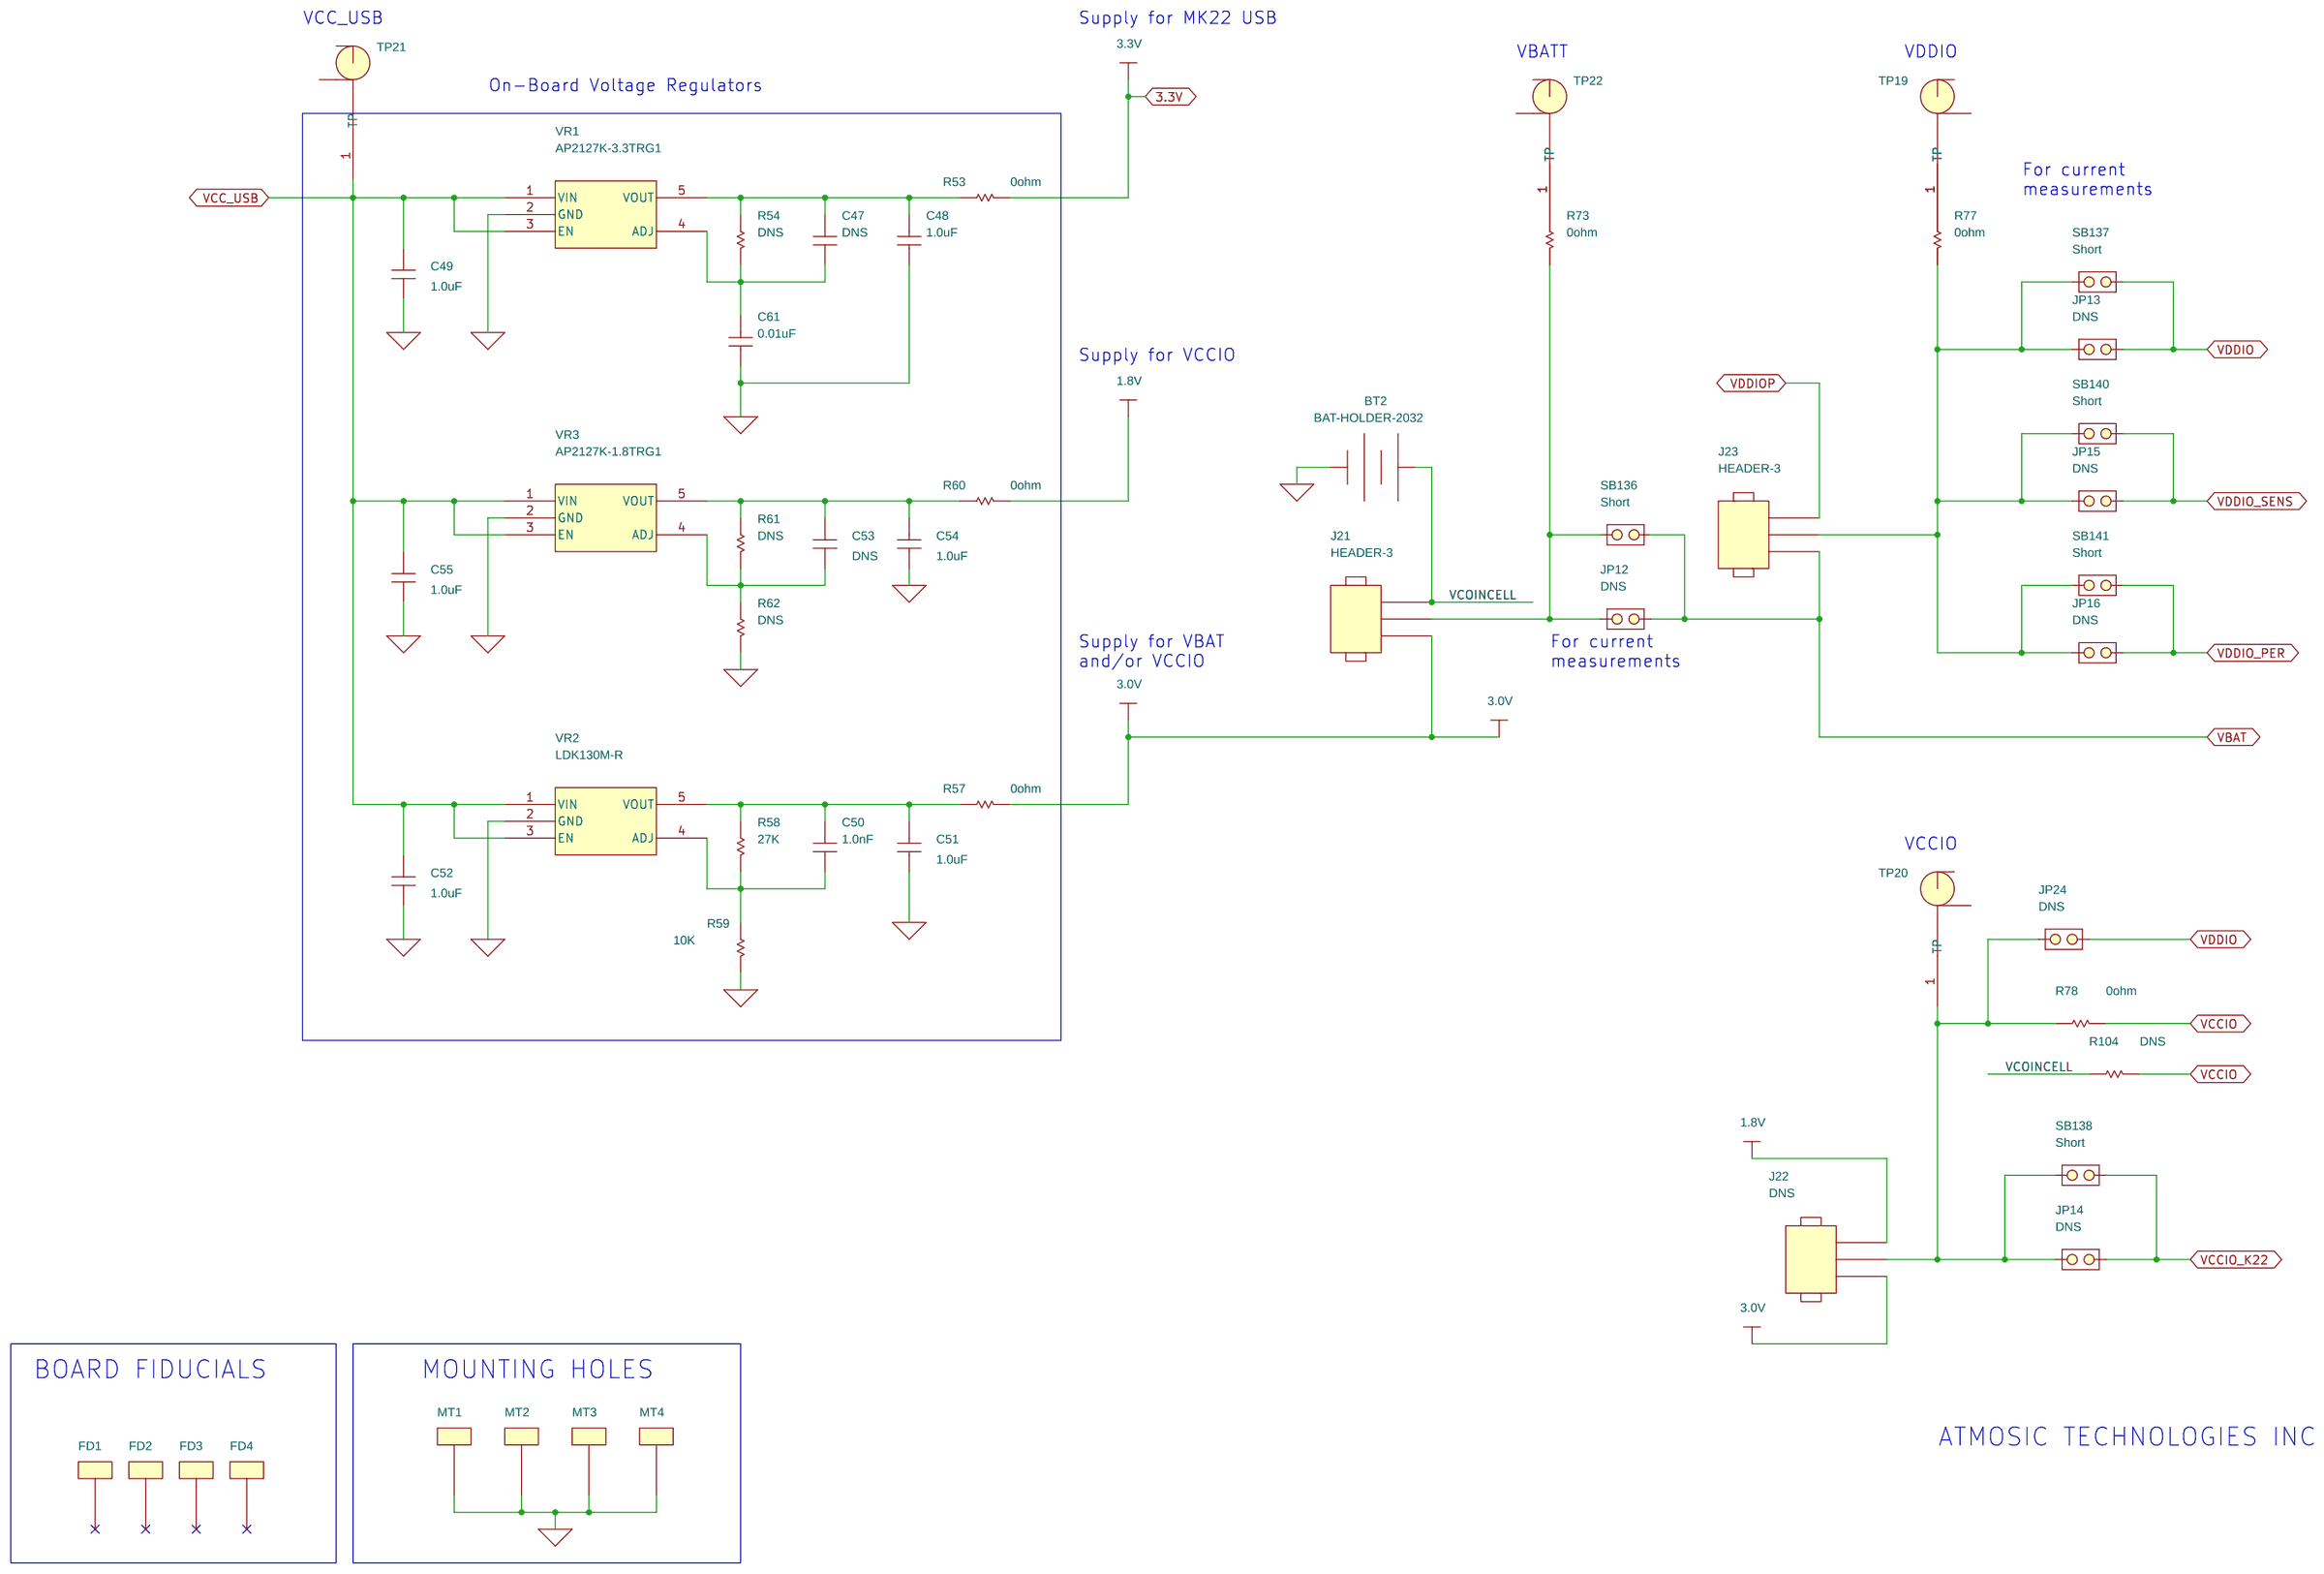
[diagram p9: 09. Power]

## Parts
sheet 03. ATM3325
C1  1.0uF  [0402]
C2  0ohm  [0402]
C3  10uF  [0402]
C4  10uF  [0402]
C5  4.7uF  [0402]
C6  1.0uF  [0402]
C7  10uF  [0402]
C10  1.0uF  [0402]
C11  1.0uF  [0402]
C12  10uF  [0603]
C13  DNS  [0603]
C17  1.0uF  [0402]
J3  DNS  [HDR1X3]
J26  HEADER-3  [HDR1X3]
JP1  DNS  [HDR1X2]
JP5  DNS  [HDR1X2]
JP26  JUMPER-2  [HDR1X2]
L1  3.3uH  [IND-2016-2]
R6  1ohm  [0402]
R8  1M  [0402]
R13  0ohm  [0402]
R15  100K  [0402]
S1  SW-TACT-4P  [SWI-SM-PTS645]
SB2  Short  [SB]
SB6  Open  [SB]
SB9  Short  [SB]
SB144  Short  [SB]
TP3  TP-BLK  [TESTPIN]
TP4  TP-BLK  [TESTPIN]
TP5  TP-BLK  [TESTPIN]
TP23  TP-BLK  [TESTPIN]
TP25  TP  [TEST2]
U1  ATM3325-LQK  [QFN-40-5X5-0.4MM]
Y1  32K XTAL  [XTAL-SMD2-2.0X1.2MM]
Y2  16M XTAL  [XTAL-ECX-2236]
sheet 04. GPIO Mapping
C56  0.1uF  [0402]
C58  0.1uF  [0402]
C59  0.1uF  [0402]
C60  0.1uF  [0402]
C72  0.1uF  [0402]
JP8  JUMPER-2  [HDR1X2]
JP11  JUMPER-2  [HDR1X2]
JP25  JUMPER-2  [HDR1X2]
JP27  JUMPER-2  [HDR1X2]
R72  1M  [0402]
R74  1M  [0402]
R79  1M  [0402]
R98  1M  [0402]
R99  1M  [0402]
R107  0ohm  [0402]
SB131  Short  [SB]
SB143  Short  [SB]
TP24  TP  [TESTPAD50]
U7  NX3DV2567  [XQFN16]
U9  NX3DV2567  [XQFN16]
U10  NX3DV2567  [XQFN16]
U11  NX3DV2567  [XQFN16]
U16  NX3DV2567  [XQFN16]
sheet 05. RF (RFIO)
C18  0ohm  [0402]
C20  1.2pF  [0402]
C21  2pF  [0402]
C22  DNS  [0402]
C65  10pF  [0402]
C66  DNS  [0201]
J4  SMA_SL  [SMA-RA]
L3  DNS  [0402]
L11  4.7nH  [0402]
L12  2.4nH  [0402]
sheet 06. Buttons LEDs Sensors
C31  0.1uF  [0402]
C32  0.1uF  [0402]
C62  DNS  [0402]
DS1  RED LED  [LED-0603]
DS2  YELLOW LED  [LED-0603]
DS3  BLUE LED  [LED-0603]
Q2  MMBT3904/SOT  [TRA-SOT23]
Q3  MMBT3904/SOT  [TRA-SOT23]
R19  1K  [0402]
R20  0ohm  [0402]
R22  0ohm  [0402]
R23  10K  [0402]
R24  100K  [0402]
R25  DNS  [0402]
R26  560  [0402]
R27  1K  [0402]
R28  470  [0402]
R29  1M  [0402]
R30  1K  [0402]
R31  1M  [0402]
R69  10K  [0402]
R71  DNS  [0402]
R84  DNS  [0402]
R85  DNS  [0402]
R97  DNS  [0402]
S2  SW-TACT-4P  [SWI-SM-PTS645]
S3  SW-TACT-4P  [SWI-SM-PTS645]
U3  LIS3DH  [LGA-16-3X3]
U4  ENS210-LQFM  [SON-04-2X2MM]
U15  DNS  [SOT23-6]
sheet 07. Connectors
C35  DNS  [0402]
C36  DNS  [0402]
C37  DNS  [0402]
C38  DNS  [0402]
C39  DNS  [0402]
C40  DNS  [0402]
J12  HEADER 25X2  [HDR25X2]
SB145  0ohm  [SB]
SB146  Open  [SB]
sheet 08. MK22
C41  0.1uF  [0402]
C42  0.1uF  [0402]
C43  0.1uF  [0402]
C44  0.1uF  [0402]
C45  0.1uF  [0402]
C46  DNS  [0402]
DS4  GREEN LED  [LED-0603]
J15  FCI 10118194-0001LF  [10118194-0001LF]
J27  DNS  [MOLEX-105133-0031]
R38  0ohm  [0402]
R39  0ohm  [0402]
R40  0ohm  [0402]
R41  0ohm  [0402]
R42  0ohm  [0402]
R43  0ohm  [0402]
R45  10K  [0402]
R46  33  [0402]
R47  33  [0402]
R48  0ohm  [0402]
R49  0ohm  [0402]
R50  0ohm  [0402]
R51  0ohm  [0402]
R66  1K  [0402]
R67  10K  [0402]
R83  10K  [0402]
TC1  DNS(TC2030-IDC)  [CON-TC2030-IDC]
TP6  TP  [TESTPAD50]
TP7  TP  [TESTPAD50]
TP8  TP  [TESTPAD50]
TP9  TP  [TESTPAD50]
TP10  TP  [TESTPAD50]
TP11  TP  [TESTPAD50]
TP13  TP  [TESTPAD50]
TP14  TP  [TESTPAD50]
TP15  TP  [TESTPAD50]
TP16  TP  [TESTPAD50]
U5  NSP4201MR6  [TSOP-6]
U6  MK22FN128VLH10  [LQFP-64-10X10-0.5MM]
sheet 09. Power
BT2  BAT-HOLDER-2032  [BAT-HOLDER-2032]
C47  DNS  [0402]
C48  1.0uF  [0402]
C49  1.0uF  [0402]
C50  1.0nF  [0402]
C51  1.0uF  [0402]
C52  1.0uF  [0402]
C53  DNS  [0402]
C54  1.0uF  [0402]
C55  1.0uF  [0402]
C61  0.01uF  [0402]
FD1  TEST POINT  [FID-G]
FD2  TEST POINT  [FID-G]
FD3  TEST POINT  [FID-G]
FD4  TEST POINT  [FID-G]
J21  HEADER-3  [HDR1X3]
J22  DNS  [HDR1X3]
J23  HEADER-3  [HDR1X3]
JP12  DNS  [HDR1X2]
JP13  DNS  [HDR1X2]
JP14  DNS  [HDR1X2]
JP15  DNS  [HDR1X2]
JP16  DNS  [HDR1X2]
JP24  DNS  [HDR1X2]
MT1  TEST POINT  [HOLE-250R125]
MT2  TEST POINT  [HOLE-250R125]
MT3  TEST POINT  [HOLE-250R125]
MT4  TEST POINT  [HOLE-250R125]
R53  0ohm  [0402]
R54  DNS  [0402]
R57  0ohm  [0402]
R58  27K  [0402]
R59  10K  [0402]
R60  0ohm  [0402]
R61  DNS  [0402]
R62  DNS  [0402]
R73  0ohm  [0402]
R77  0ohm  [0402]
R78  0ohm  [0402]
R104  DNS  [0402]
SB136  Short  [SB]
SB137  Short  [SB]
SB138  Short  [SB]
SB140  Short  [SB]
SB141  Short  [SB]
TP19  TP-WHT  [TESTPIN]
TP20  TP-WHT  [TESTPIN]
TP21  TP-WHT  [TESTPIN]
TP22  TP-WHT  [TESTPIN]
VR1  AP2127K-3.3TRG1  [SOT23-5]
VR2  LDK130M-R  [SOT23-5]
VR3  AP2127K-1.8TRG1  [SOT23-5]
sheet 10. VCCIO Source
C74  1.0uF  [0402]
C75  0.1uF  [0402]
Q5  BSS84PW  [SOT-323]
R108  100K  [0402]
R109  93.1K  [0402]
R110  50  [0402]
R111  DNS  [0402]
R112  0ohm  [0402]
R113  0ohm  [0402]
U17  MCP6001  [SC70]
U18  TMUX1237  [SC70-6]
U19  MCP6001  [SC70]
U20  MCP6001  [SC70]
U21  MCP6001  [SC70]

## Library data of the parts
C1 C6 C10 C11 C48 C49 C51 C52 C54 C55 = SMALL_CAP: Manufacture_Name: MURATA; Manufacture_Part_Number: GRT155R61E105ME01D; Part Number: 01-2000007; Price: 0.003; Vendor: MURATA
C2 = SMALL_CAP: Manufacture_Name: PANASONIC; Manufacture_Part_Number: ERJ-2GE0R00X; Part Number: 01-2000027; Price: 0.0002; Vendor: MURATA
C3 C4 C7 = SMALL_CAP: Manufacture_Name: MURATA; Manufacture_Part_Number: GRM155R60J106ME15D; Part Number: 01-2000011; Price: 0.006; Vendor: MURATA
C5 = SMALL_CAP: Manufacture_Name: TDK; Manufacture_Part_Number: CL05A475MO5NUNC; Part Number: 01-2000015; Price: 0,003; Vendor: TDK
C12 = SMALL_CAP: Manufacture_Name: MURATA; Manufacture_Part_Number: GRM185R60J106ME15J; Part Number: 01-3000002; Price: 0.013; Vendor: MURATA
C13 C22 C35-C40 C46 C47 C53 C62 C66 = SMALL_CAP
C17 C74 = SMALL_CAP: Manufacture_Name: MURATA; Manufacture_Part_Number: GRT155R61E105ME01D; Part Number: 01-2000007; Price: 0.003
J3 = HEADER_3
J21 J23 J26 = HEADER_3: Manufacture_Name: AMPHENOL ICC (FCI); Manufacture_Part_Number: 68001-203HLF; Part Number: 08-0000003; Vendor: AMPHENOL ICC (FCI)
JP1 JP5 JP12-JP16 JP24 = JUMPER-2
JP8 JP11 JP25-JP27 = JUMPER-2: Manufacture_Name: AMPHENOL ICC (FCI); Manufacture_Part_Number: 68000-102HLF; Part Number: 08-0000002; Vendor: AMPHENOL ICC (FCI)
L1 = INDUCTOR: Manufacture_Name: MURATA; Manufacture_Part_Number: LQM2MPN3R3NG0L; Part Number: 02-4000002; Price: 0.04; Vendor: MURATA
R6 = SMALL_R1: Manufacture_Name: YAGEO; Manufacture_Part_Number: RC0402FR-071RL; Part Description: RES 1 OHM 1% 1/16W 0402; Part Number: 03-2000032; Price: 0.0007; Vendor: YAGEO
R8 R29 R31 R72 R74 R79 R98 R99 = SMALL_R1: Manufacture_Name: YAGEO; Manufacture_Part_Number: RC0402JR-071ML; Part Number: 03-2000030; Price: 0.0007; Vendor: YAGEO
R13 R20 R22 R38 R39 R41-R43 R48-R51 R53 R57 R60 R73 R77 R78 = SMALL_R1: Manufacture_Name: PANASONIC; Manufacture_Part_Number: ERJ-2GE0R00X; Part Number: 03-2000018; Price: 0.00046; Vendor: PANASONIC
R15 R24 = SMALL_R1: Manufacture_Name: YAGEO; Manufacture_Part_Number: RC0402JR-07100KL; Part Number: 03-2000020; Price: 0.00053; Vendor: YAGEO
S1-S3 = SW-TACT-4P-5: Manufacture_Name: C&K; Manufacture_Part_Number: PTS645SK50SMTR92 LFS; Part Number: 07-0000017; Vendor: C&K
SB2 SB6 SB9 SB131 SB136-SB138 SB140 SB141 SB143 SB144 SB146 = SB
TP3-TP5 TP23 = TP: Manufacture_Name: KEYSTONE ELECTRONICS; Manufacture_Part_Number: 36-5011-ND; Part Number: 08-0000006; Vendor: KEYSTONE ELECTRONICS
TP25 = TP_0: Part Number: 09-0000001
U1 = PARIS_ATM3325_QFN5X5_3: Manufacture_Name: Atmosic; Manufacture_Part_Number: ATM3325; Part Number: 04-0000002; Vendor: ATMOSIC
Y1 = XTAL: Manufacture_Name: SEIKO; Manufacture_Part_Number: SC20S-7PF20PPM; Part Number: 06-0000018; Vendor: SEIKO
Y2 = XTAL-OSC-4P_0: Manufacture_Name: ECS; Manufacture_Part_Number: ECS-160-8-36-JTN-TR; Part Number: 06-0000013; Price: 0.13; Vendor: ECS
C31 C32 C41-C45 C56 C58-C60 C72 C75 = SMALL_CAP: Manufacture_Name: TAIYO-YUDEN; Manufacture_Part_Number: TMK105BJ104KV-F; Part Number: 01-2000003; Price: 0.0013; Vendor: TAIYO-YUDEN
R107 = SMALL_R1: Manufacture_Name: WALSIN; Manufacture_Part_Number: WR04X000PTL; Part Number: 03-2000001; Vendor: YAGEO
TP6-TP11 TP13-TP16 TP24 = TP_0
U7 U9-U11 U16 = NX3DV2567: Manufacture_Name: NXP; Manufacture_Part_Number: NX3DV2567GU115; Part Number: 05-0000007; Vendor: NXP
C18 = SMALL_CAP: Manufacture_Name: PANASONIC; Manufacture_Part_Number: ERJ-2GE0R00X; Part Number: 01-2000027; Price: 0.0002; Vendor: PANASONIC
C20 = SMALL_CAP: Manufacture_Name: JOHANSON; Manufacture_Part_Number: 500R07S1R2BV4T; Part Number: 01-2000031; Price: 0.001; Vendor: JOHANSON
C21 = SMALL_CAP: Manufacture_Name: JOHANSON; Manufacture_Part_Number: 500R07S2R0BV4T; Part Number: 01-2000032; Price: 0.001; Vendor: JOHANSON
C65 = SMALL_CAP: Manufacture_Name: JOHANSON; Manufacture_Part_Number: 500R07S100JV4T; Part Number: 01-2000010; Price: 0.001; Vendor: JOHANSON
J4 = SMA_SL: Manufacture_Name: CINCH CONNECTIVITY SOLUTIONS JOHNSON; Manufacture_Part_Number: 142-0701-801; Part Number: 08-0000005; Vendor: CINCH CONNECTIVITY SOLUTIONS JOHNSON
L3 = INDUCTOR
L11 = INDUCTOR: Manufacture_Name: TDK; Manufacture_Part_Number: MHQ1005P4N7BT000; Part Description: FIXED IND 4.7NH ∮0.1nH 800MA 110MOHM SM; Part Number: 02-2000012; Vendor: TDK
L12 = INDUCTOR: Manufacture_Name: TDK; Manufacture_Part_Number: MHQ1005P2N4BT000; Part Description: FIXED IND 2.4NH ∮0.1nH 1A 60 MOHM SMD; Part Number: 02-2000018; Vendor: TDK
DS1 = LED: Manufacture_Name: WURTH ELEKTRONIK; Manufacture_Part_Number: 150060RS75000; Part Number: 06-0000016; Vendor: WURTH ELEKTRONIK
DS2 = LED: Manufacture_Name: WURTH ELEKTRONIK; Manufacture_Part_Number: 150060YS75000; Part Number: 06-0000017; Vendor: WURTH ELEKTRONIK
DS3 = LED: Manufacture_Name: WURTH ELEKTRONIK; Manufacture_Part_Number: 150060BS75000; Part Number: 06-0000014; Vendor: WURTH ELEKTRONIK
Q2 Q3 = MMBT3904_SOT: Manufacture_Name: NEXPERIA; Manufacture_Part_Number: PMBT3904-215; Part Number: 06-0000022; Vendor: nexperia
R19 R27 R30 R66 = SMALL_R1: Manufacture_Name: WALSIN; Manufacture_Part_Number: WR04X1001FTL; Part Description: RES 1K OHM 1% 0402; Part Number: 03-2000028; Price: 0.00053; Vendor: CYNTEC
R23 R45 R59 R67 R69 R83 = SMALL_R1: Manufacture_Name: YAGEO; Manufacture_Part_Number: RC0402JR-0710KL; Part Number: 03-2000021; Price: 0.00053; Vendor: YAGEO
R25 R54 R61 R62 R71 R84 R85 R97 R104 R111 = SMALL_R1
R26 = SMALL_R1: Manufacture_Name: YAGEO; Manufacture_Part_Number: RC0402JR-07560RL; Part Number: 03-2000015; Price: 0.00053; Vendor: YAGEO
R28 = SMALL_R1: Manufacture_Name: YAGEO; Manufacture_Part_Number: RC0402JR-07470RL; Part Number: 03-2000012; Price: 0.00053; Vendor: YAGEO
U3 = LIS3DHTR_0: Manufacture_Name: STMicroelectronics; Part Description: ACCEL 2-16G I2C/SPI 16LGA; Part Number: 05-0000003; Price: 0.84; Vendor: ATMOSIC
U4 = ENS210-LQFM_2: Manufacture_Name: SCIOSENSE; Part Number: 05-0000005; Vendor: SCIOSENSE
U15 = 24AA014_0
J12 = HEADER_25X2: Manufacture_Name: AMPHENOL ICC (FCI); Manufacture_Part_Number: 67996-150HLF; Part Number: 08-0000004; Vendor: AMPHENOL ICC (FCI)
SB145 = SB: Manufacture_Name: PANASONIC; Manufacture_Part_Number: ERJ-2GE0R00X; Part Number: 03-2000004
DS4 = LED: Manufacture_Name: WURTH ELEKTRONIK; Manufacture_Part_Number: 150060GS75000; Part Number: 06-0000015; Vendor: WURTH ELEKTRONIK
J15 = USB_CONN_1_v2: Manufacture_Name: AMPHENOL ICC (FCI); Part Number: 07-0000004; Vendor: AMPHENOL ICC (FCI)
J27 = USB_CONN_1
R40 R112 R113 = SMALL_R1: Manufacture_Name: PANASONIC; Manufacture_Part_Number: ERJ-2GE0R00X; Part Number: 03-2000018; Price: 0.00046
R46 R47 = SMALL_R1: Manufacture_Name: YAGEO; Manufacture_Part_Number: RC0402JR-0733RL; Part Number: 03-2000003; Price: 0.00053; Vendor: YAGEO
TC1 = TC2030-IDC
U5 = NSP4201MR6_0: Manufacture_Name: ON Semiconductor; Part Description: TVS DIODE 5VWM 12VC 6TSOP; Part Number: 05-0000006; Vendor: ATMOSIC
U6 = MK22FN128VLH10_0: Manufacture_Name: NXP; Part Description: IC MCU 32BIT 128KB FLASH 64LQFP; Part Number: 05-0000004; Vendor: ATMOSIC
BT2 = BAT: Part Number: 08-0000015
C50 = SMALL_CAP: Manufacture_Name: TDK; Manufacture_Part_Number: CGA2B2NP01H102J050BA; Part Number: 01-2000005; Price: 0.01; Vendor: TDK
C61 = SMALL_CAP: Manufacture_Name: TDK; Manufacture_Part_Number: CGA2B3X7R1H103K050BB; Part Number: 01-2000001; Price: 0.0016; Vendor: TDK
FD1-FD4 MT1-MT4 = TEST_POINT
J22 = HEADER_3: Vendor: AMPHENOL ICC (FCI)
R58 = SMALL_R1: Manufacture_Name: YAGEO; Manufacture_Part_Number: RC0402FR-0727KL; Part Number: 03-2000033; Price: 0.00053; Vendor: YAGEO
TP19-TP22 = TP: Manufacture_Name: KEYSTONE ELECTRONICS; Manufacture_Part_Number: 36-5012-ND; Part Number: 08-0000007; Vendor: KEYSTONE ELECTRONICS
VR1 = VAR_REG: Manufacture_Name: DIODES; Part Number: 06-0000020; Vendor: DIODES
VR2 = VAR_REG: Manufacture_Name: STMICROELECTRONICS; Part Number: 06-0000021; Vendor: STMICROELECTRONICS
VR3 = VAR_REG: Manufacture_Name: DIODES; Manufacture_Part_Number: AP2127K-1-8TRG1; Part Number: 06-0000019; Vendor: DIODES
Q5 = BSS84_SOT_0: Part Description: PMOS; Part Number: 06-0000057
R108 = SMALL_R1: Manufacture_Name: YAGEO; Manufacture_Part_Number: RC0402JR-07100KL; Part Number: 03-2000020; Price: 0.00053
R109 = SMALL_R1: Manufacture_Name: YAGEO; Manufacture_Part_Number: RC0402FR-0793K1L; Part Description: RES 93.1K OHM 1% 0402; Part Number: 03-2000071; Price: 0.00053
R110 = SMALL_R1: Manufacture_Name: YAGEO; Manufacture_Part_Number: RC0402JR-0750RL; Part Description: RES 50 OHM 5% 1/16W 0402; Part Number: 03-2000072; Price: 0.00053
U17 U19-U21 = MCP6001: Part Number: 05-0000021
U18 = TMUX1237: Part Number: 05-0000022

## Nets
1.8V: J22.3 R60.2
3.0V: J21.1 J22.1 R57.2
3.3V: C39.2 C40.1 C45.1 J12.26 R26.2 R28.2 R53.2 R109.1 U6.7(USBVDD)
AVDD1: C12.1 C13.1 R6.1 U1.1(AVDD1)
AVDD1P: C4.1 JP5.1 SB9.1 U1.18(AVDD1P)
AVDDPA: J3.2 R13.1 SB144.1
DVDD1: C1.1 JP1.2 SB2.2 U1.21(DVDD1)
DVDD1P: C3.1 JP1.1 SB2.1 U1.20(DVDD1P)
GND_SIGNAL: BT2.2(NEG) C1.2 C2.2 C3.2 C4.2 C5.2 C6.2 C7.2 C10.2 C11.2 C12.2 C13.2 C17.2 C20.1 C21.1 C22.2 C31.2 C32.2 C35.1 C36.2 C37.1 C38.2 C39.1 C40.2 C41.2 C42.2 C43.2 C44.2 C45.2 C46.2 C48.1 C49.1 C51.1 C52.1 C54.1 C55.1 C56.2 C58.2 C59.2 C60.2 C61.1 C62.2 C66.2 C72.2 C74.2 C75.2 DS1.1(CATHODE) J4.2(GND1) J4.3(GND2) J12.1 J12.27 J15.5(GND) J15.S1(CASE) J15.S2(CASE) J15.S3(CASE) J15.S4(CASE) J15.S5(CASE) J15.S6(CASE) J27.5(GND) J27.S1(CASE) J27.S2(CASE) J27.S3(CASE) MT1.1 MT2.1 MT3.1 MT4.1 Q2.2(E) Q3.2(E) R8.1 R15.1 R25.1 R29.1 R45.1 R59.2 R62.2 R72.1 R74.1 R79.1 R98.1 R99.1 R108.2 R111.2 S3.3 S3.4 SB6.2 TC1.5(GND) TP3.1(TP) TP4.1(TP) TP5.1(TP) TP23.1(TP) U1.41(EGND) U3.5(GND) U3.10(RES) U3.12(GND_1) U4.4(VSS) U4.5(VSS_1) U5.2(GND) U6.4(VSS) U6.15(VREFL) U6.16(VSSA) U6.31(VSS) U6.32(PTA18) U6.33(PTA19) U6.47(VSS) U7.6(GND) U9.6(GND) U10.6(GND) U11.6(GND) U15.2(VSS) U15.4(A1) U16.6(GND) U17.2 U18.5(S6) U19.2 U20.2 U21.2 VR1.2(GND) VR2.2(GND) VR3.2(GND) Y2.2(NC) Y2.4(NC)
VBAT: C7.1 J23.1 J26.1 JP12.1 SB136.1 U1.13(VBAT)
VCC_S: C62.1 R20.2 R22.2 R23.1 R24.1 R31.2 R69.2 R71.2 R84.2 R85.2 R97.2 S2.3 S2.4 U10.15(1Y1) U15.6(VCC)
VCC_USB: C49.2 C52.2 C55.2 C75.1 DS4.2(ANODE) J15.1(VBUS) J27.1(VBUS) Q5.2(S) TP21.1(TP) U5.5(VP) U17.5 U18.2(VDD) U19.5 U20.5 U21.5 VR1.1(VIN) VR1.3(EN) VR2.1(VIN) VR2.3(EN) VR3.1(VIN) VR3.3(EN)
VCCIO: C56.1 C58.1 C59.1 C60.1 C72.1 J26.3 JP8.1 JP11.1 JP25.1 JP27.1 R78.2 R104.2 R113.2 SB145.2 U7.14(VCC) U9.14(VCC) U10.14(VCC) U11.14(VCC) U16.14(VCC)
VCCIO_K22: C41.1 C42.1 C43.1 C44.1 JP14.1 SB138.1 TC1.1(VCC) U6.3(VDD) U6.13(VDDA) U6.14(VREFH) U6.21(VBAT) U6.26(PTA4/LLWU_P3) U6.30(VDD) U6.48(VDD)
VDDIO: C10.1 C11.1 JP13.1 JP24.1 R112.1 SB137.1 U1.6(VDDIO) U1.28(VDDIO)
VDDIO_PER: JP16.1 SB141.1 SB146.2
VDDIO_SENS: JP15.1 SB140.1 U10.16(1Z)
VDDIOP: C6.1 J3.1 J23.3 JP26.2 SB144.2 U1.17(VDDIOP)
BBOOT: R66.1 U9.13(4Y0)
BUTTON_1: R29.2 S2.1 S2.2 SB131.2
BUTTON_2: R31.1 S3.1 S3.2 U16.15(1Y1)
DM: R46.1 U6.6(USB0_DM)
DP: R47.1 U6.5(USB0_DP)
FLASH_CS_IN: U1.24(FLASH_CS_IN) U1.25(FLASH_CS_OUT)
G_INT: U3.11(INT1) U10.11(4Y1)
I2C0_SCK: R71.1 R97.1 U3.4(SCL/SPC) U4.2(SCL) U10.7(3Y1) U15.1(SCL)
I2C0_SDA: R69.1 R84.1 U3.6(SDA/SDI/SDO) U4.3(SDA) U10.3(2Y1) U15.3(SDA)
LED_1: R19.2 U16.3(2Y1)
LED_2: R27.1 U16.7(3Y1)
LED_3: R30.1 U16.11(4Y1)
NO_K22: JP11.2 R74.2 R83.1 SB143.1 U7.2(S)
P0: J12.32 U1.4(P0) U9.4(2Z)
P1: J12.33 U1.5(P1) U9.8(3Z)
P3: J12.35 U1.7(P3) U16.16(1Z)
P4: J12.36 U1.8(P4) U10.8(3Z)
P5: J12.37 U1.9(P5) U10.4(2Z)
P7: J12.39 U1.10(P7) U16.8(3Z)
P8: J12.40 SB131.1 U1.11(P8)
P14: J12.6 U1.26(P14) U10.12(4Z)
P17: J12.9 U1.29(P17) U7.16(1Z)
P18: J12.10 U1.30(P18)
P19: J12.11 U1.31(P19) U7.4(2Z)
P20: J12.12 U1.32(P20) U7.12(4Z)
P21: J12.13 U1.33(P21) U11.8(3Z)
P22: J12.14 U1.34(P22)
P25: J12.17 R15.2 R107.2 U1.35(P25) U9.12(4Z)
P27: J12.22 U1.38(P27) U11.4(2Z)
P29: J12.24 U1.39(P29) U16.4(2Z)
P30: J12.25 U1.40(P30) U7.8(3Z)
PWD: J12.49 R8.2 R67.1 S1.1 S1.2 U1.12(PWD)
RFIO: L11.2 U1.2(RFIO)
SWDCLK_K22: R39.1 U9.5(2Y0)
SWDIO_K22: R38.1 U9.9(3Y0)
UART0_CTS_K22: R51.1 U7.13(4Y0)
UART0_RTS_K22: R50.1 U7.1(1Y0)
UART0_RX_K22: R48.1 U7.9(3Y0)
UART0_TX_K22: R49.1 U7.5(2Y0)
UART1_CTS_K22: R43.1 TP7.1(TP)
UART1_RTS_K22: R42.1 TP6.1(TP)
UART1_RX_K22: R40.1 U11.9(3Y0)
UART1_TX_K22: R41.1 U11.5(2Y0)
UART2_CTS_K22: TP11.1(TP) U6.44(PTC1/LLWU_P6)
UART2_RTS_K22: TP10.1(TP) U6.45(PTC2)
UART2_RX_K22: TP8.1(TP) U6.49(PTC4/LLWU_P8)
UART2_TX_K22: TP9.1(TP) U6.46(PTC3/LLWU_P7)
USB_D+: J15.3(D+) J27.3(D+) R47.2 U5.3(IO2) U5.4(IO3)
USB_D-: J15.2(D-) J27.2(D-) R46.2 U5.1(IO1) U5.6(IO4)
VAUX: C5.1 JP26.1 U1.19(VAUX)
VCOINCELL: BT2.1(POS) J21.3 R104.1
VSTORE: C2.1 J3.3 U1.15(VSTORE)
XTALI_16M: U1.37(XTALO_16M) Y2.1(HOT)
XTALI_32K: SB6.1 U1.23(XTALI_32K) Y1.2
XTALO_16M: U1.36(XTALI_16M) Y2.3(HOT)
XTALO_32K: U1.22(XTALO_32K) Y1.1
N16735640: JP5.2 R6.2 SB9.2
N16873328: L1.1 U1.14(LEXT1)
N16873338: L1.2 U1.16(LEXT2)
N16893506: C17.1 R13.2 U1.3(VDDPA)
N16962530: C35.2 C36.1 C37.2 C38.1 J12.2 J12.50 SB145.1 SB146.1
N17095028: C47.2 C48.2 R53.1 R54.1 VR1.5(VOUT)
N17095050: C47.1 C61.2 R54.2 VR1.4(ADJ)
N17095106: J21.2 JP12.2 R73.1 SB136.2
N17095108: J23.2 JP13.2 JP15.2 JP16.2 R77.2 SB137.2 SB140.2 SB141.2
N17095279: C53.2 C54.2 R60.1 R61.1 VR3.5(VOUT)
N17095319: C53.1 R61.2 R62.1 VR3.4(ADJ)
N17095531: C50.2 C51.2 R57.1 R58.1 VR2.5(VOUT)
N17095557: C50.1 R58.2 R59.1 VR2.4(ADJ)
N17096185: J22.2 JP14.2 JP24.2 R78.1 SB138.2 TP20.1(TP)
N17100046: R99.2 SB143.2 TP24.1(TP) U9.2(S)
N17100334: JP25.2 R72.2 U10.2(S)
N17101171: C18.2 J4.1(IO)
N17101173: C18.1 C65.2 C66.1 L3.1
N17101183: C20.2 C65.1 L12.1
N17101189: C21.2 L11.1 L12.2
N17101247: C22.1 L3.2
N17102737: DS1.2(ANODE) R19.1
N17102803: C31.1 R20.1 U3.1(VDD_IO) U3.14(Vdd)
N17102805: C32.1 R22.1 U4.1(VDD)
N17102917: DS2.2(ANODE) R26.1
N17102919: DS2.1(CATHODE) Q2.3(C)
N17103005: R23.2 R25.2 U3.7(SDO/SA0)
N17103017: Q2.1(B) R27.2
N17103021: R24.2 U3.8(CS)
N17103073: DS3.2(ANODE) R28.1
N17103075: DS3.1(CATHODE) Q3.3(C)
N17103123: Q3.1(B) R30.2
N17103574: R85.1 U15.5(A0)
N17105483: R67.2 U6.2(PTE1/LLWU_P0)
N17105496: R83.2 TP15.1(TP) U6.58(PTD1)
N17105530: R38.2 U6.63(PTD6/LLWU_P15)
N17105555: R39.2 U6.62(PTD5)
N17105589: R66.2 U6.61(PTD4/LLWU_P14)
N17105614: R40.2 U6.60(PTD3)
N17105656: R41.2 U6.59(PTD2/LLWU_P13)
N17105670: R42.2 U6.54(PTC9)
N17105708: R43.2 U6.53(PTC8)
N17105834: DS4.1(CATHODE) R45.2
N17106014: R48.2 U6.40(PTB17)
N17106031: R49.2 U6.39(PTB16)
N17106052: R50.2 U6.38(PTB3)
N17106071: R51.2 U6.37(PTB2)
N17106085: C46.1 TC1.3(NRESET) U6.34(RESET_B)
N17106116: TC1.4(SWCLK) U6.22(PTA0)
N17106118: TC1.6(SWO) U6.24(PTA2)
N17106120: TC1.2(SWDIO) U6.25(PTA3)
N17109714: J26.2 S1.3 S1.4
N17114657: JP27.2 R98.2 U16.2(S)
N17183908: R107.1 U16.12(4Z)
N17230676: R108.1 R109.2 U17.3
N17230689: U18.1(S2) U19.3 U20.1 U20.4
N17230697: U18.6(SEL) U19.1
N17230701: U17.1 U17.4 U18.3(S1) U19.4
N17230792: Q5.3(D) R111.1 R113.1 U21.3
N17230798: R112.2 U20.3
N17230810: Q5.1(G) U21.1
N17230827: R110.2 U18.4(D)
N17230829: C74.1 R110.1 U21.4
N17237313: JP8.2 R79.2 U11.2(S)
N17260660: R73.2 TP22.1(TP)
N17260661: R77.1 TP19.1(TP)
N17261683: TP16.1(TP) U6.64(PTD7)
N17261684: TP14.1(TP) U6.57(PTC0/LLWU_P12)
N17261685: TP13.1(TP) U6.56(PTC11/LLWU_P11)
N17266371: TP25.1(TP) U1.27(NC)

Not connected (* = marked no-connect by the designer): FD1 1*; FD2 1*; FD3 1*; FD4 1*; J12 3* 4* 5* 7* 8* 15* 16* 18* 19* 20* 21* 23* 28* 29* 30* 31* 34* 38* 41* 42* 43* 44* 45* 46* 47* 48*; J15 4(IO)*; J27 4(IO)*; U3 2(NC)* 3(NC_1)* 9(INT2)* 13(ADC3)* 15(ADC2)* 16(ADC1)*; U6 1(PTE0/CLKOUT32K)* 8(NC)* 9(ADC0_DP0/ADC1_DP3)* 10(ADC0_DM0/ADC1_DM3)* 11(ADC1_DP0/ADC0_DP3)* 12(ADC1_DM0/ADC0_DM3)* 17(VREF_OUT)* 18(DAC0_OUT)* 19(XTAL32)* 20(EXTAL32)* 23(PTA1)* 27(PTA5)* 28(PTA12)* 29(PTA13/LLWU_P4)* 35(PTB0/LLWU_P5)* 36(PTB1)* 41(PTB18)* 42(PTB19)* 43(PTC0)* 50(PTC5/LLWU_P9)* 51(PTC6/LLWU_P10)* 52(PTC7)* 55(PTC10)*; U7 3(2Y1)* 7(3Y1)* 10(N_C_)* 11(4Y1)* 15(1Y1)*; U9 1(1Y0)* 3(2Y1)* 7(3Y1)* 10(N_C_)* 11(4Y1)* 15(1Y1)* 16(1Z)*; U10 1(1Y0)* 5(2Y0)* 9(3Y0)* 10(N_C_)* 13(4Y0)*; U11 1(1Y0)* 3(2Y1)* 7(3Y1)* 10(N_C_)* 11(4Y1)* 12(4Z)* 13(4Y0)* 15(1Y1)* 16(1Z)*; U16 1(1Y0)* 5(2Y0)* 9(3Y0)* 10(N_C_)* 13(4Y0)*

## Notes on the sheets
sheet 1
- ATMOSIC TECHNOLOGIES INC
sheet 2
- ATM3325 w/ EXTENDED STORAGE EVALUATION BOARD (with J-Link OB)
- Release Date
- Revision
- Design Eng.
- Design Notes
- 2/16/23
- -3.0
- Afan Lin
- Initial release
- 2/16/23
- -3.1
- Afan Lin
- Modified the description for C12
- Atmosic Technologies, Inc
- ATMOSIC TECHNOLOGIES INC
- Atmosic Technologies Proprietary and Confidential
sheet 3
- Block Diagram
- LEDs
- Buttons
- Sensors
- Programming
  Pads
- Power Supplies
- USB
  Connector
- Analog
  Switches
- MK22
- BLE Tx/Rx
  Match
- SMA Conn
- 50-pin
  Connector
- Power Supplies
- ATM3325
- Reset Button
- ATMOSIC TECHNOLOGIES INC
sheet 4
- Change C2 to 10uF if
  VSTORE needs to be used.
- Change C12 to 22uF if needs
  to operate below -10¢J
- 16MHz XTAL
- Power down switch
- PTS645 SMD
- Benign boot
- 5X5 QFN
- ATMOSIC TECHNOLOGIES INC
- Atmosic Technologies Proprietary and Confidential
sheet 5
- GPIO MUX
- CONNECT SENSORS TO ATM3325
- ISOLATE MK22 FROM ATM3325
- Install to
  connect Sensors
- Install to
  isolate MK22
- Install to
  isolate MK22
- CONNECT LEDS/BUTTONS TO ATM3325
- Assert to
  isolate MK22
- Install to
  connect LEDs
  and Buttons
- ATMOSIC TECHNOLOGIES INC
- Atmosic Technologies Proprietary and Confidential
sheet 6
- BLE front-end match
- Note:
  For inductors, use MHQ series from TDK.
  For capacitors, use Johanson
- RFIO
- ESD150-B1-W0201
- ATMOSIC TECHNOLOGIES INC
- Atmosic Technologies Proprietary and Confidential
sheet 7
- MOTION SENSOR
- LEDS
- BIDS (1Kbits)
- SA0: I2C less significant bit of the device address.
  High: 0x19
  Default: input with internal pull-up
- The I2C slave device address: 0x51
- TEMP/HUM SENSOR
- 24AA014
- PUSH BUTTONS
- The I2C slave device address of ENS210: 0x43
- PTS645 SMD
- PTS645 SMD
- ATMOSIC TECHNOLOGIES INC
sheet 8
- 50-PIN CONNECTOR
- ATMOSIC TECHNOLOGIES INC
sheet 9
- USB ESD
- (Benign Boot)
- 90 OHM DIFF PAIR
- USB
- USB OPTION
- J-Link OB
  Programming Pads
- ATMOSIC TECHNOLOGIES INC
sheet 10
- VCC_USB
- Supply for MK22 USB
- VBATT
- VDDIO
- On-Board Voltage Regulators
- For current
  measurements
- Supply for VCCIO
- Supply for VBAT
  and/or VCCIO
- For current
  measurements
- VCCIO
- BOARD FIDUCIALS
- MOUNTING HOLES
- ATMOSIC TECHNOLOGIES INC
